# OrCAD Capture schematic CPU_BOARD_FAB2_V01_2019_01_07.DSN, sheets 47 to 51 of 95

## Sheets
47 024 BDX-DE LPC,SPI,GPIO,INT_1: size B
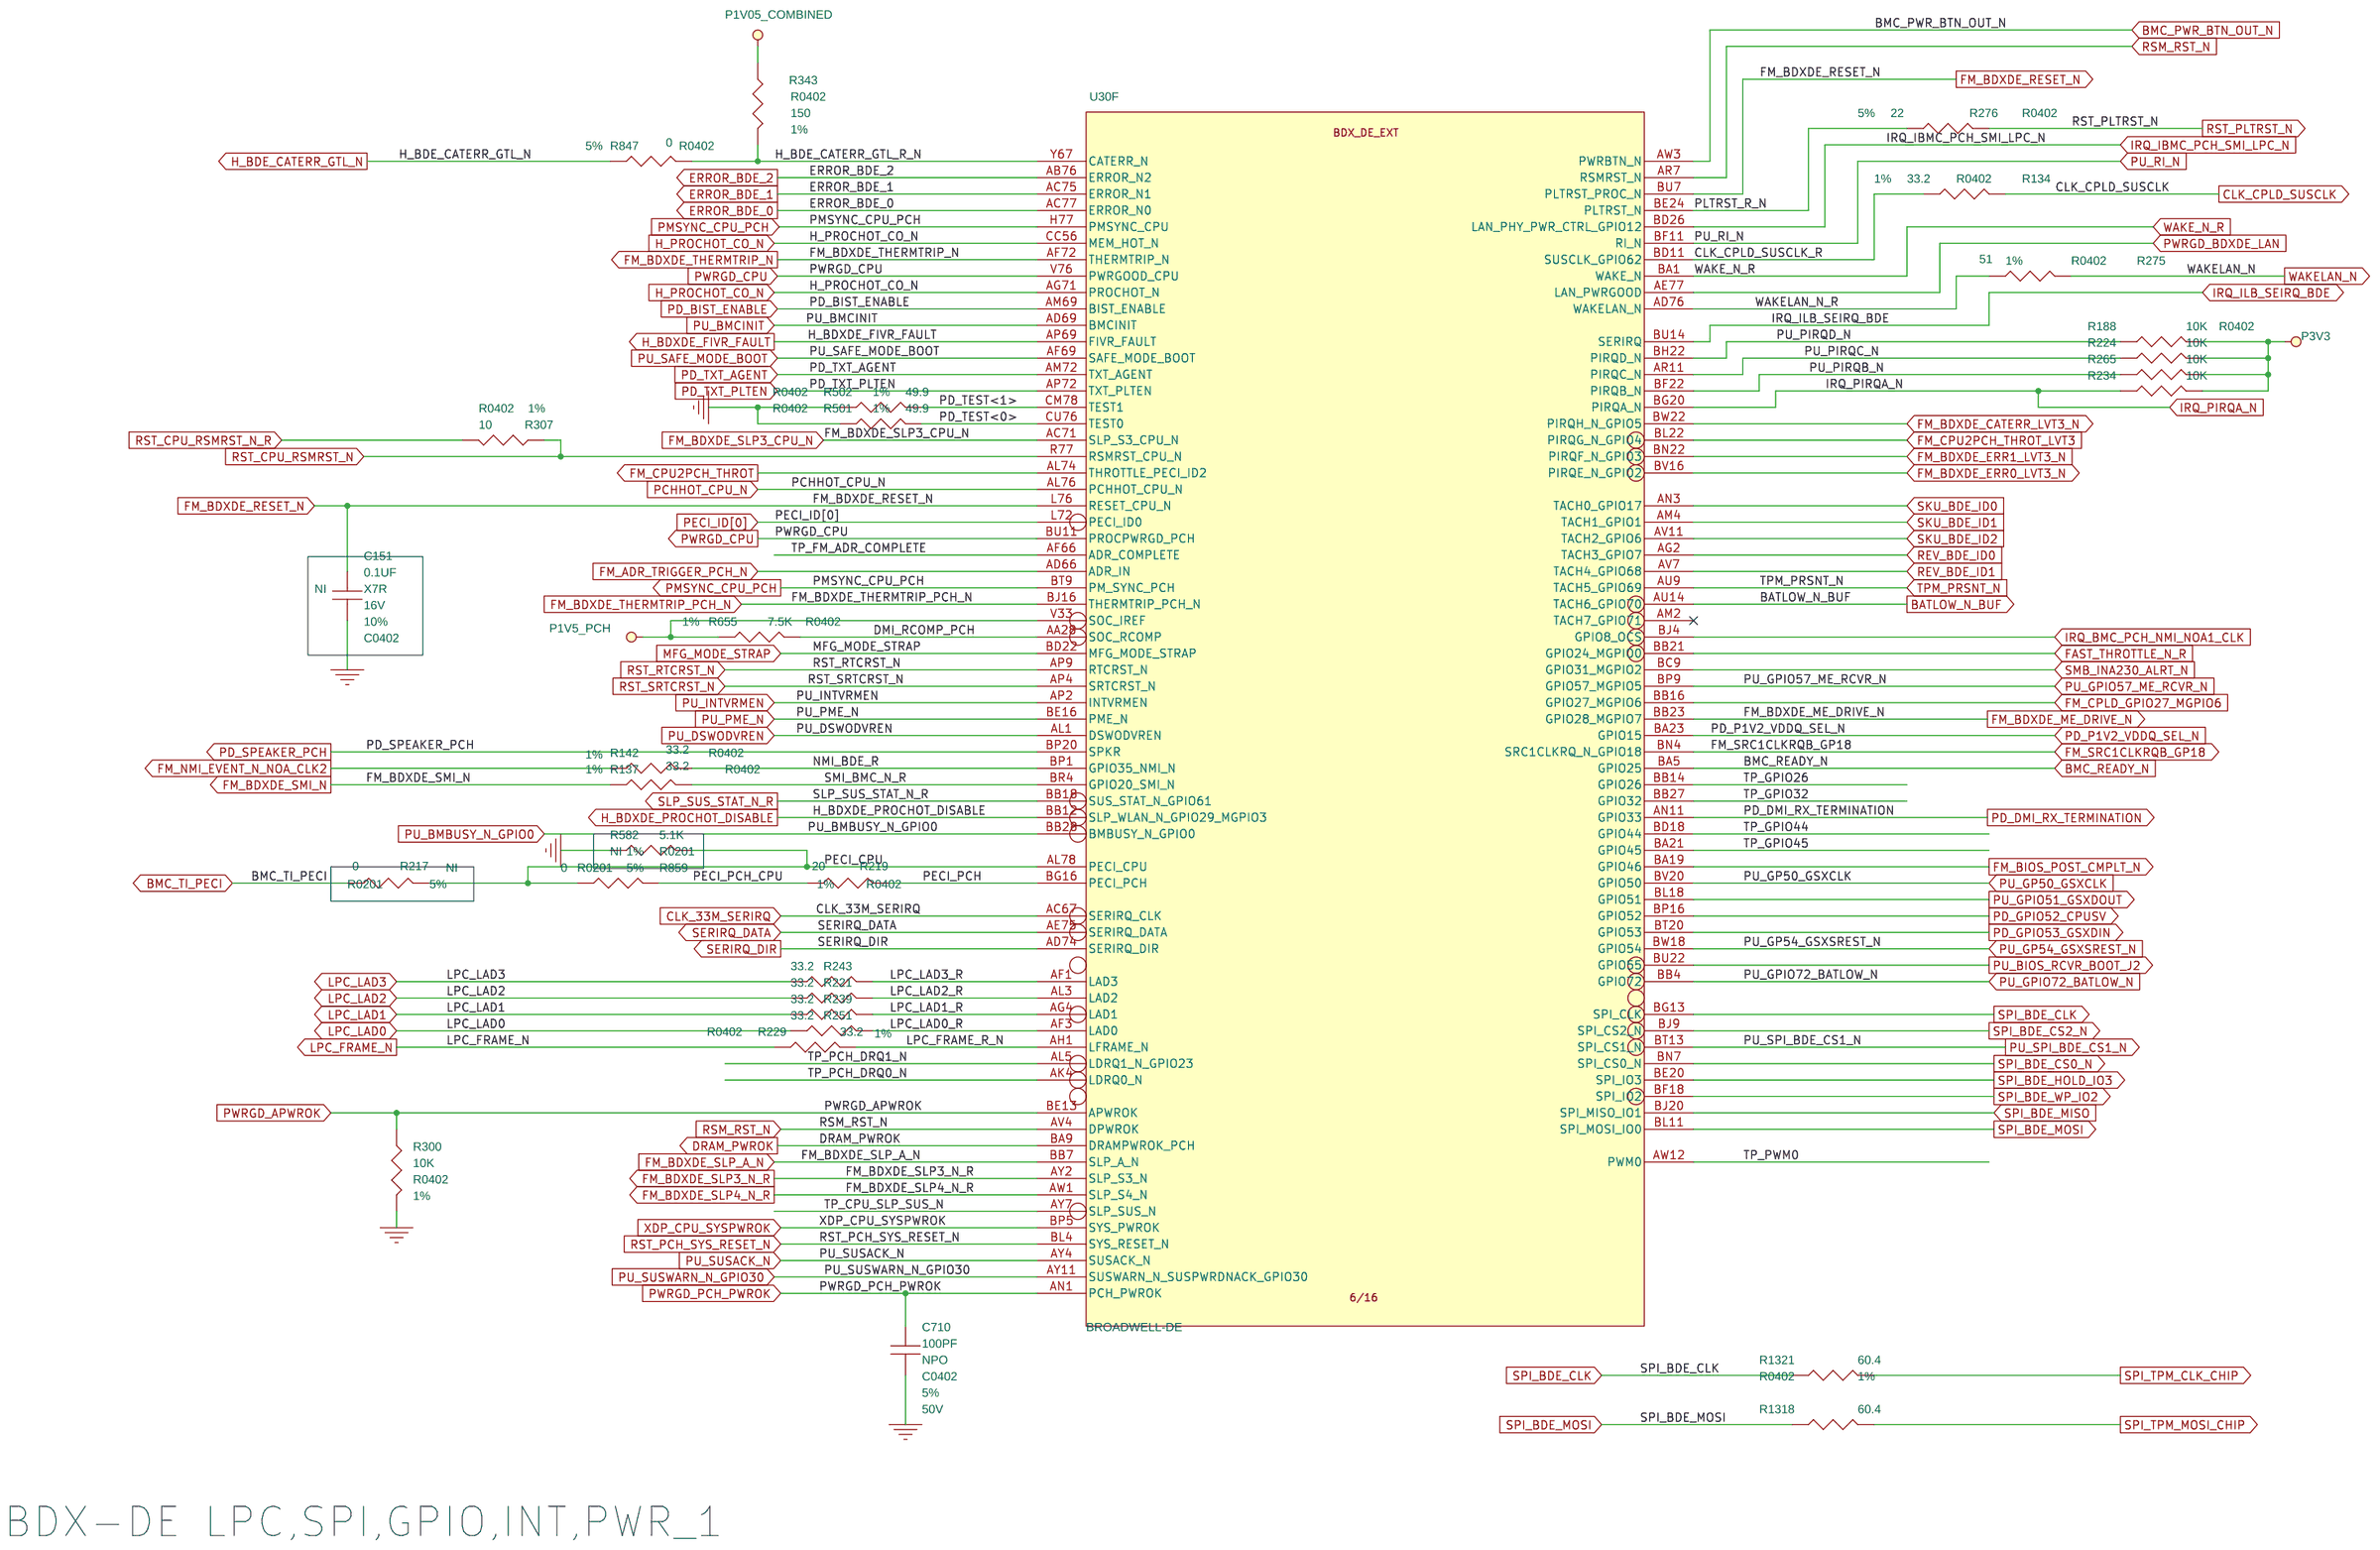
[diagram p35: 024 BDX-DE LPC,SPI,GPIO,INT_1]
48 026 BDX-DE UART,MGNT,INT,SVID_1: size B
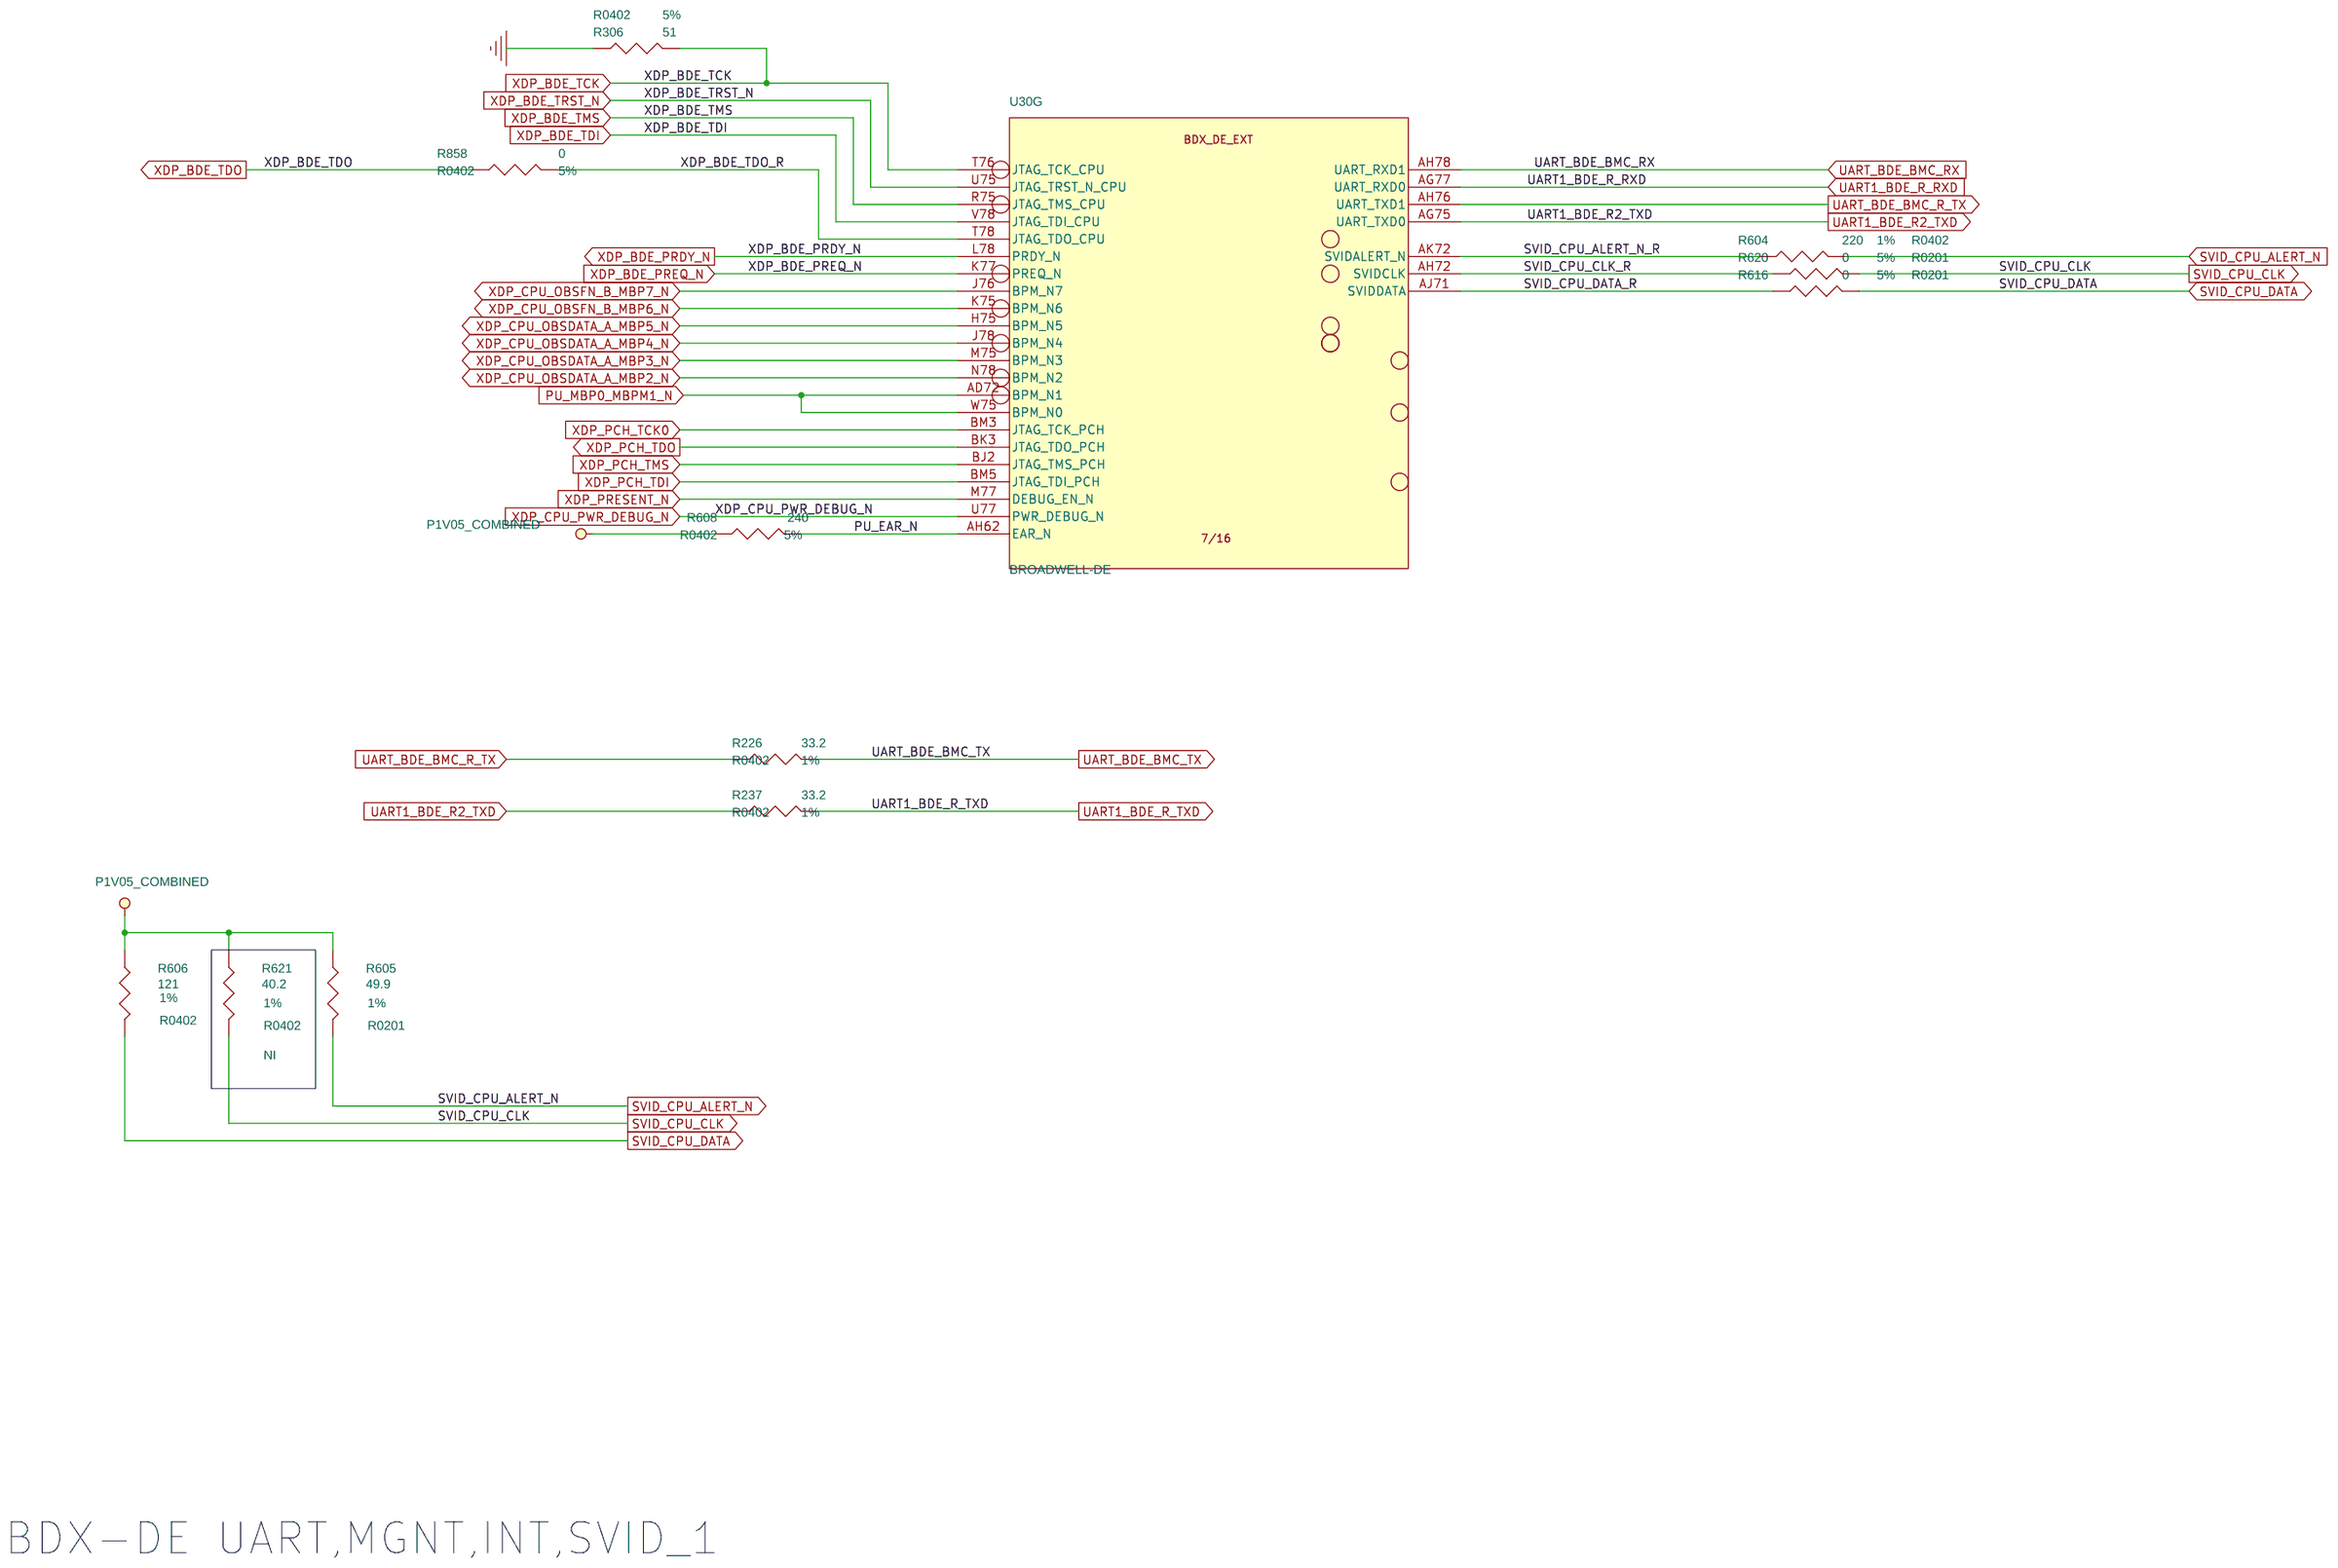
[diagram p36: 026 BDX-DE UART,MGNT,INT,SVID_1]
49 028 BDX-DE CLK: size B
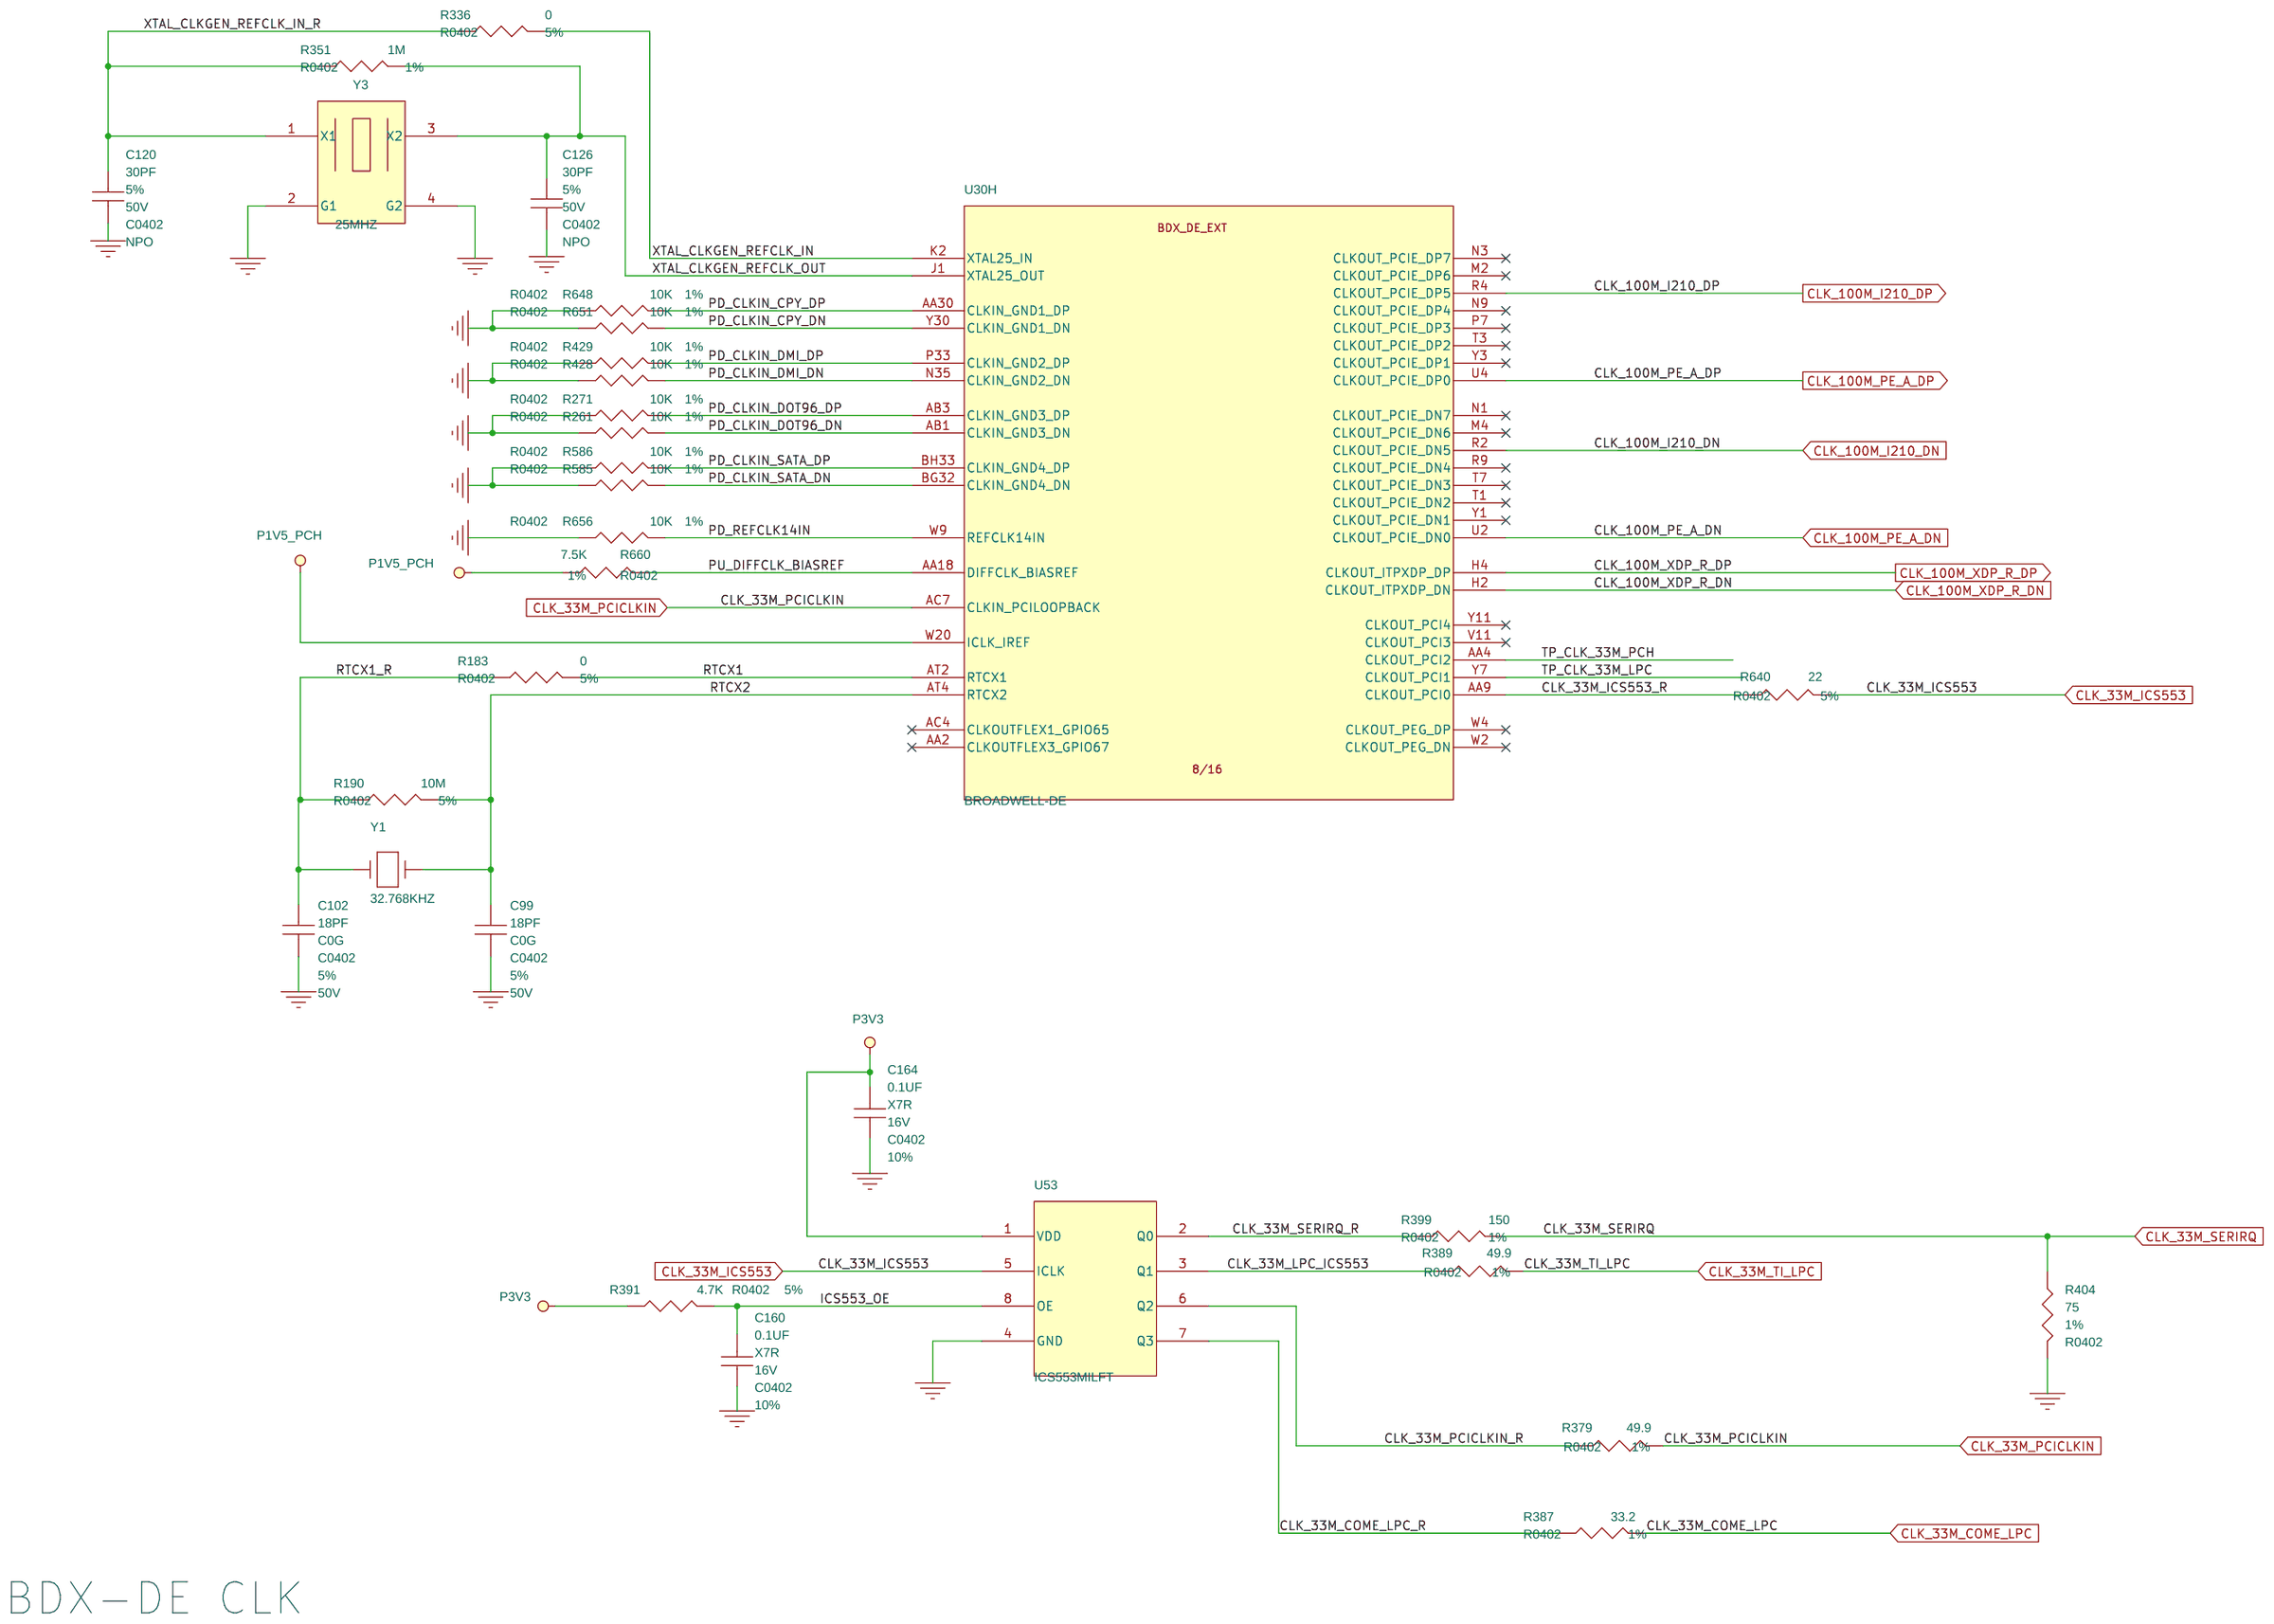
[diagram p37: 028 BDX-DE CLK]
50 029 BDX-DE TEST: size B
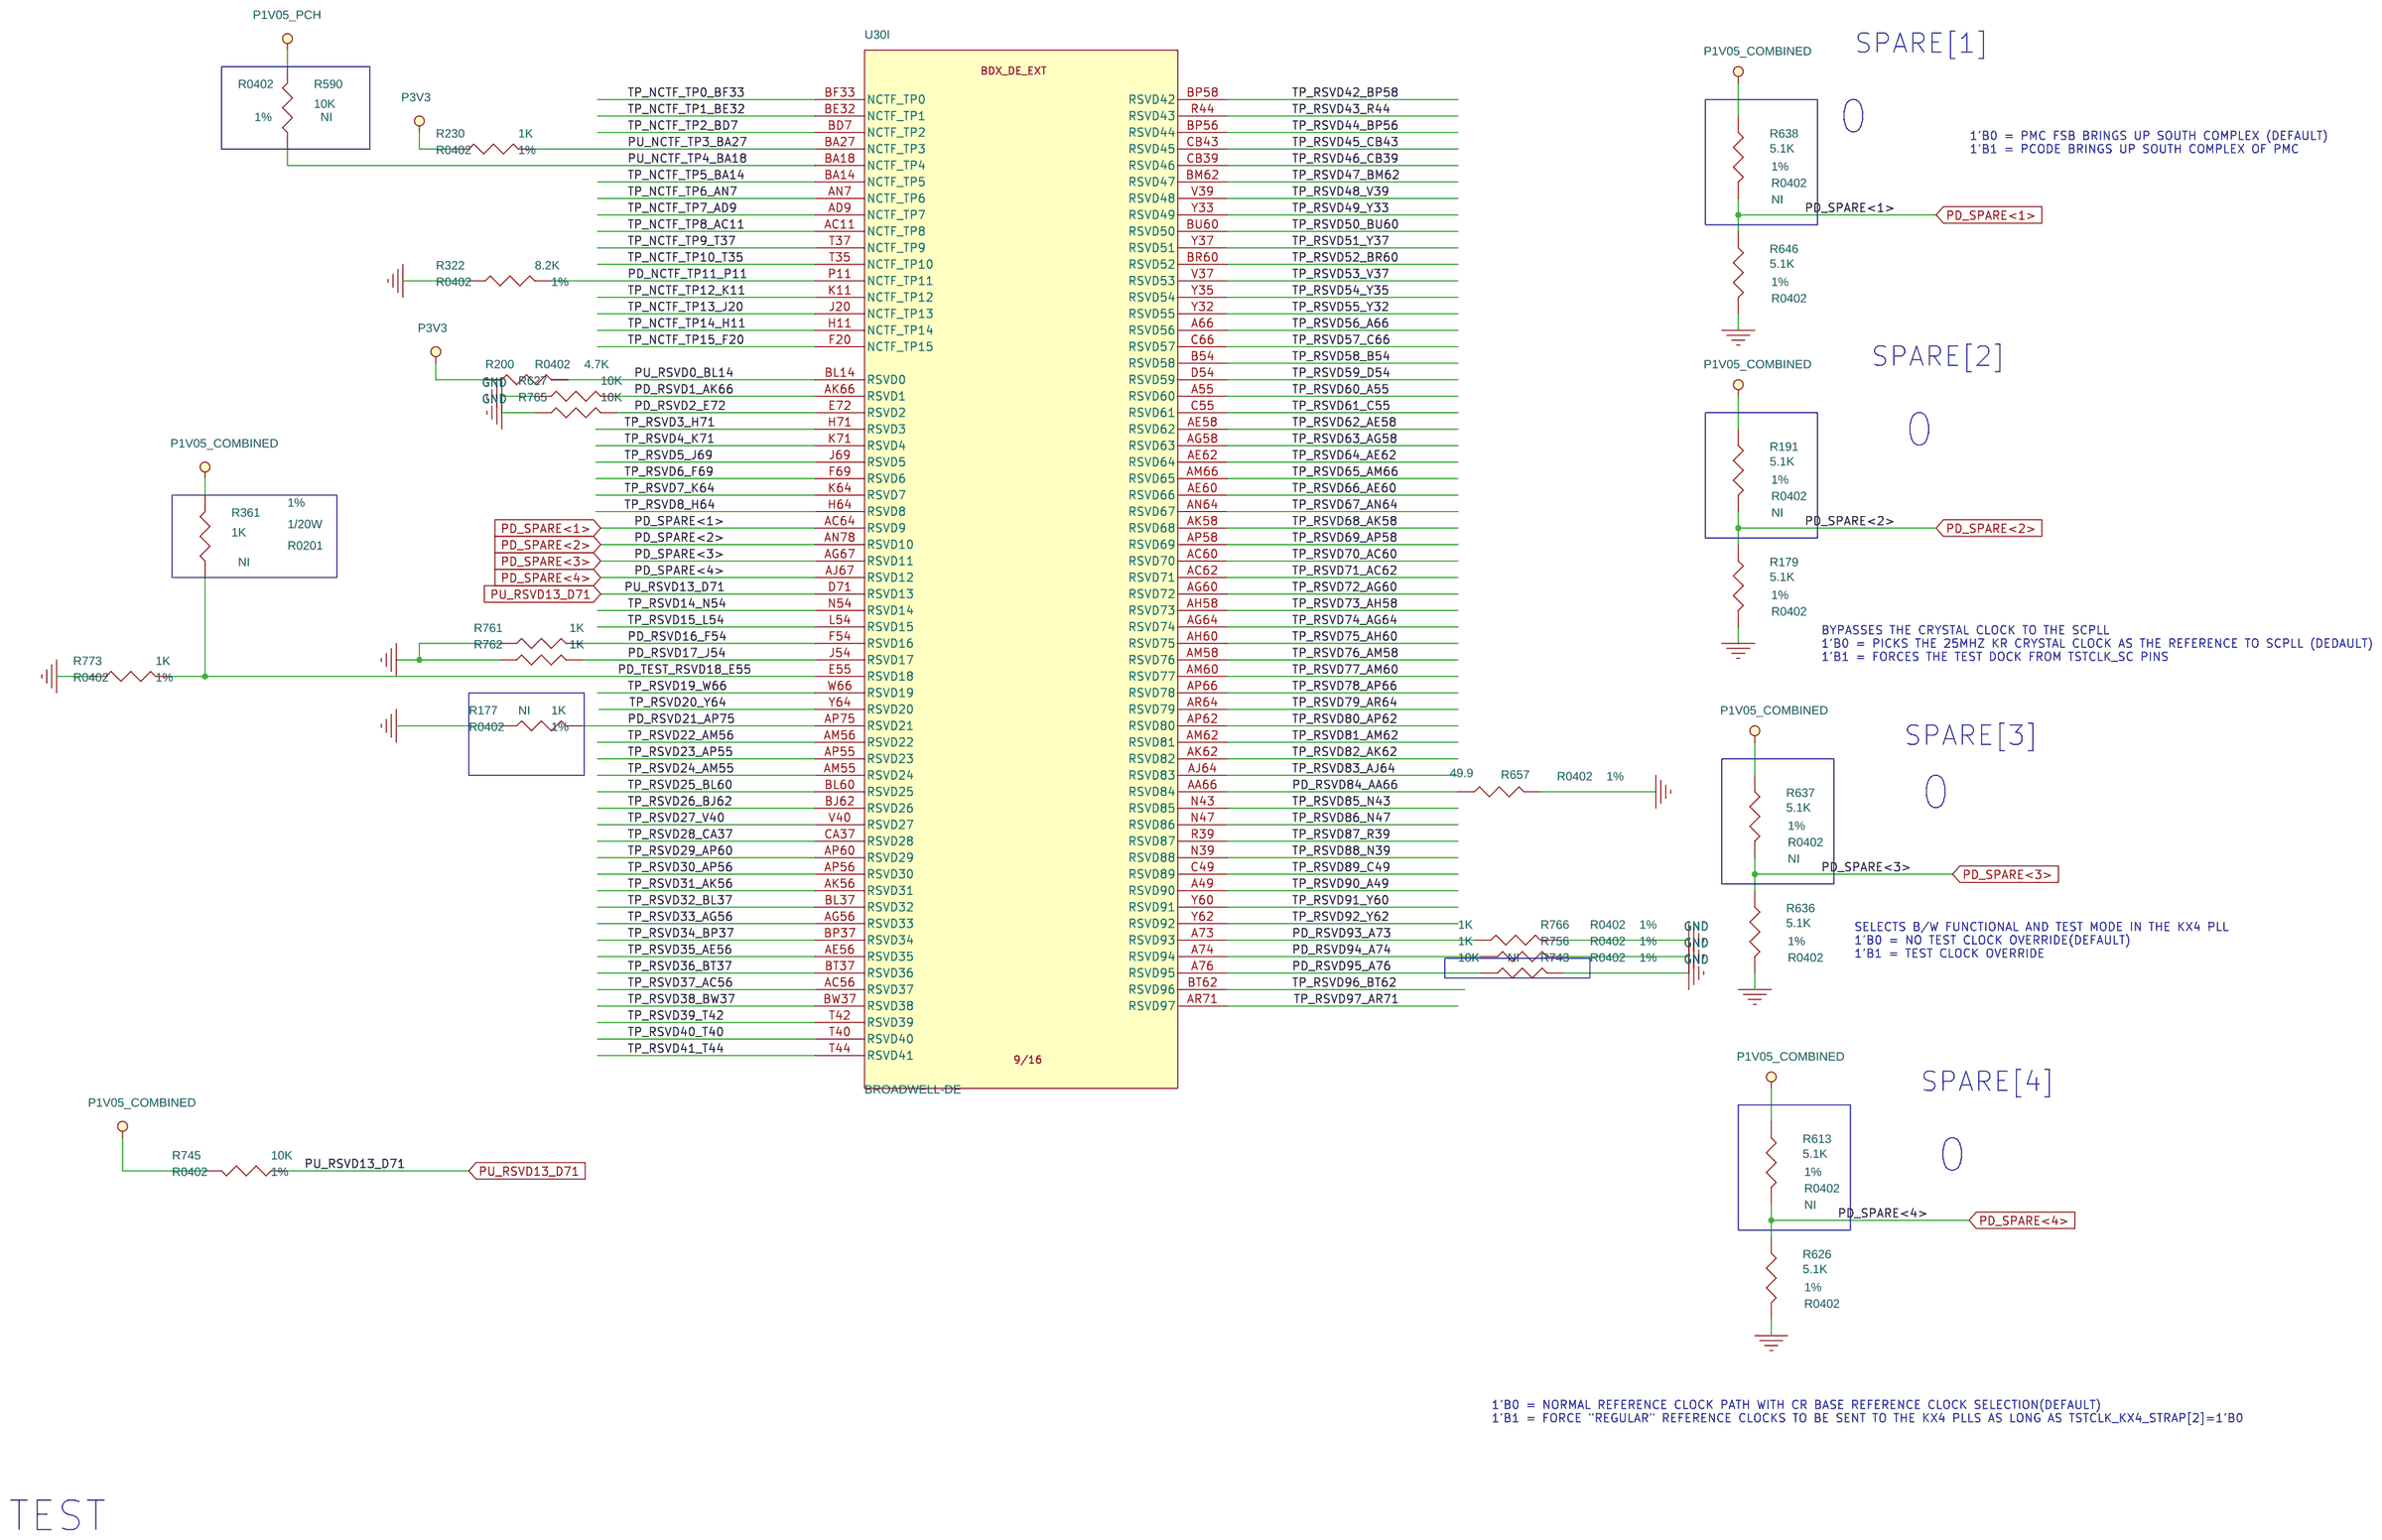
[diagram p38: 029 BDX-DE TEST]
51 031 BDX-DE POWER_1: size B
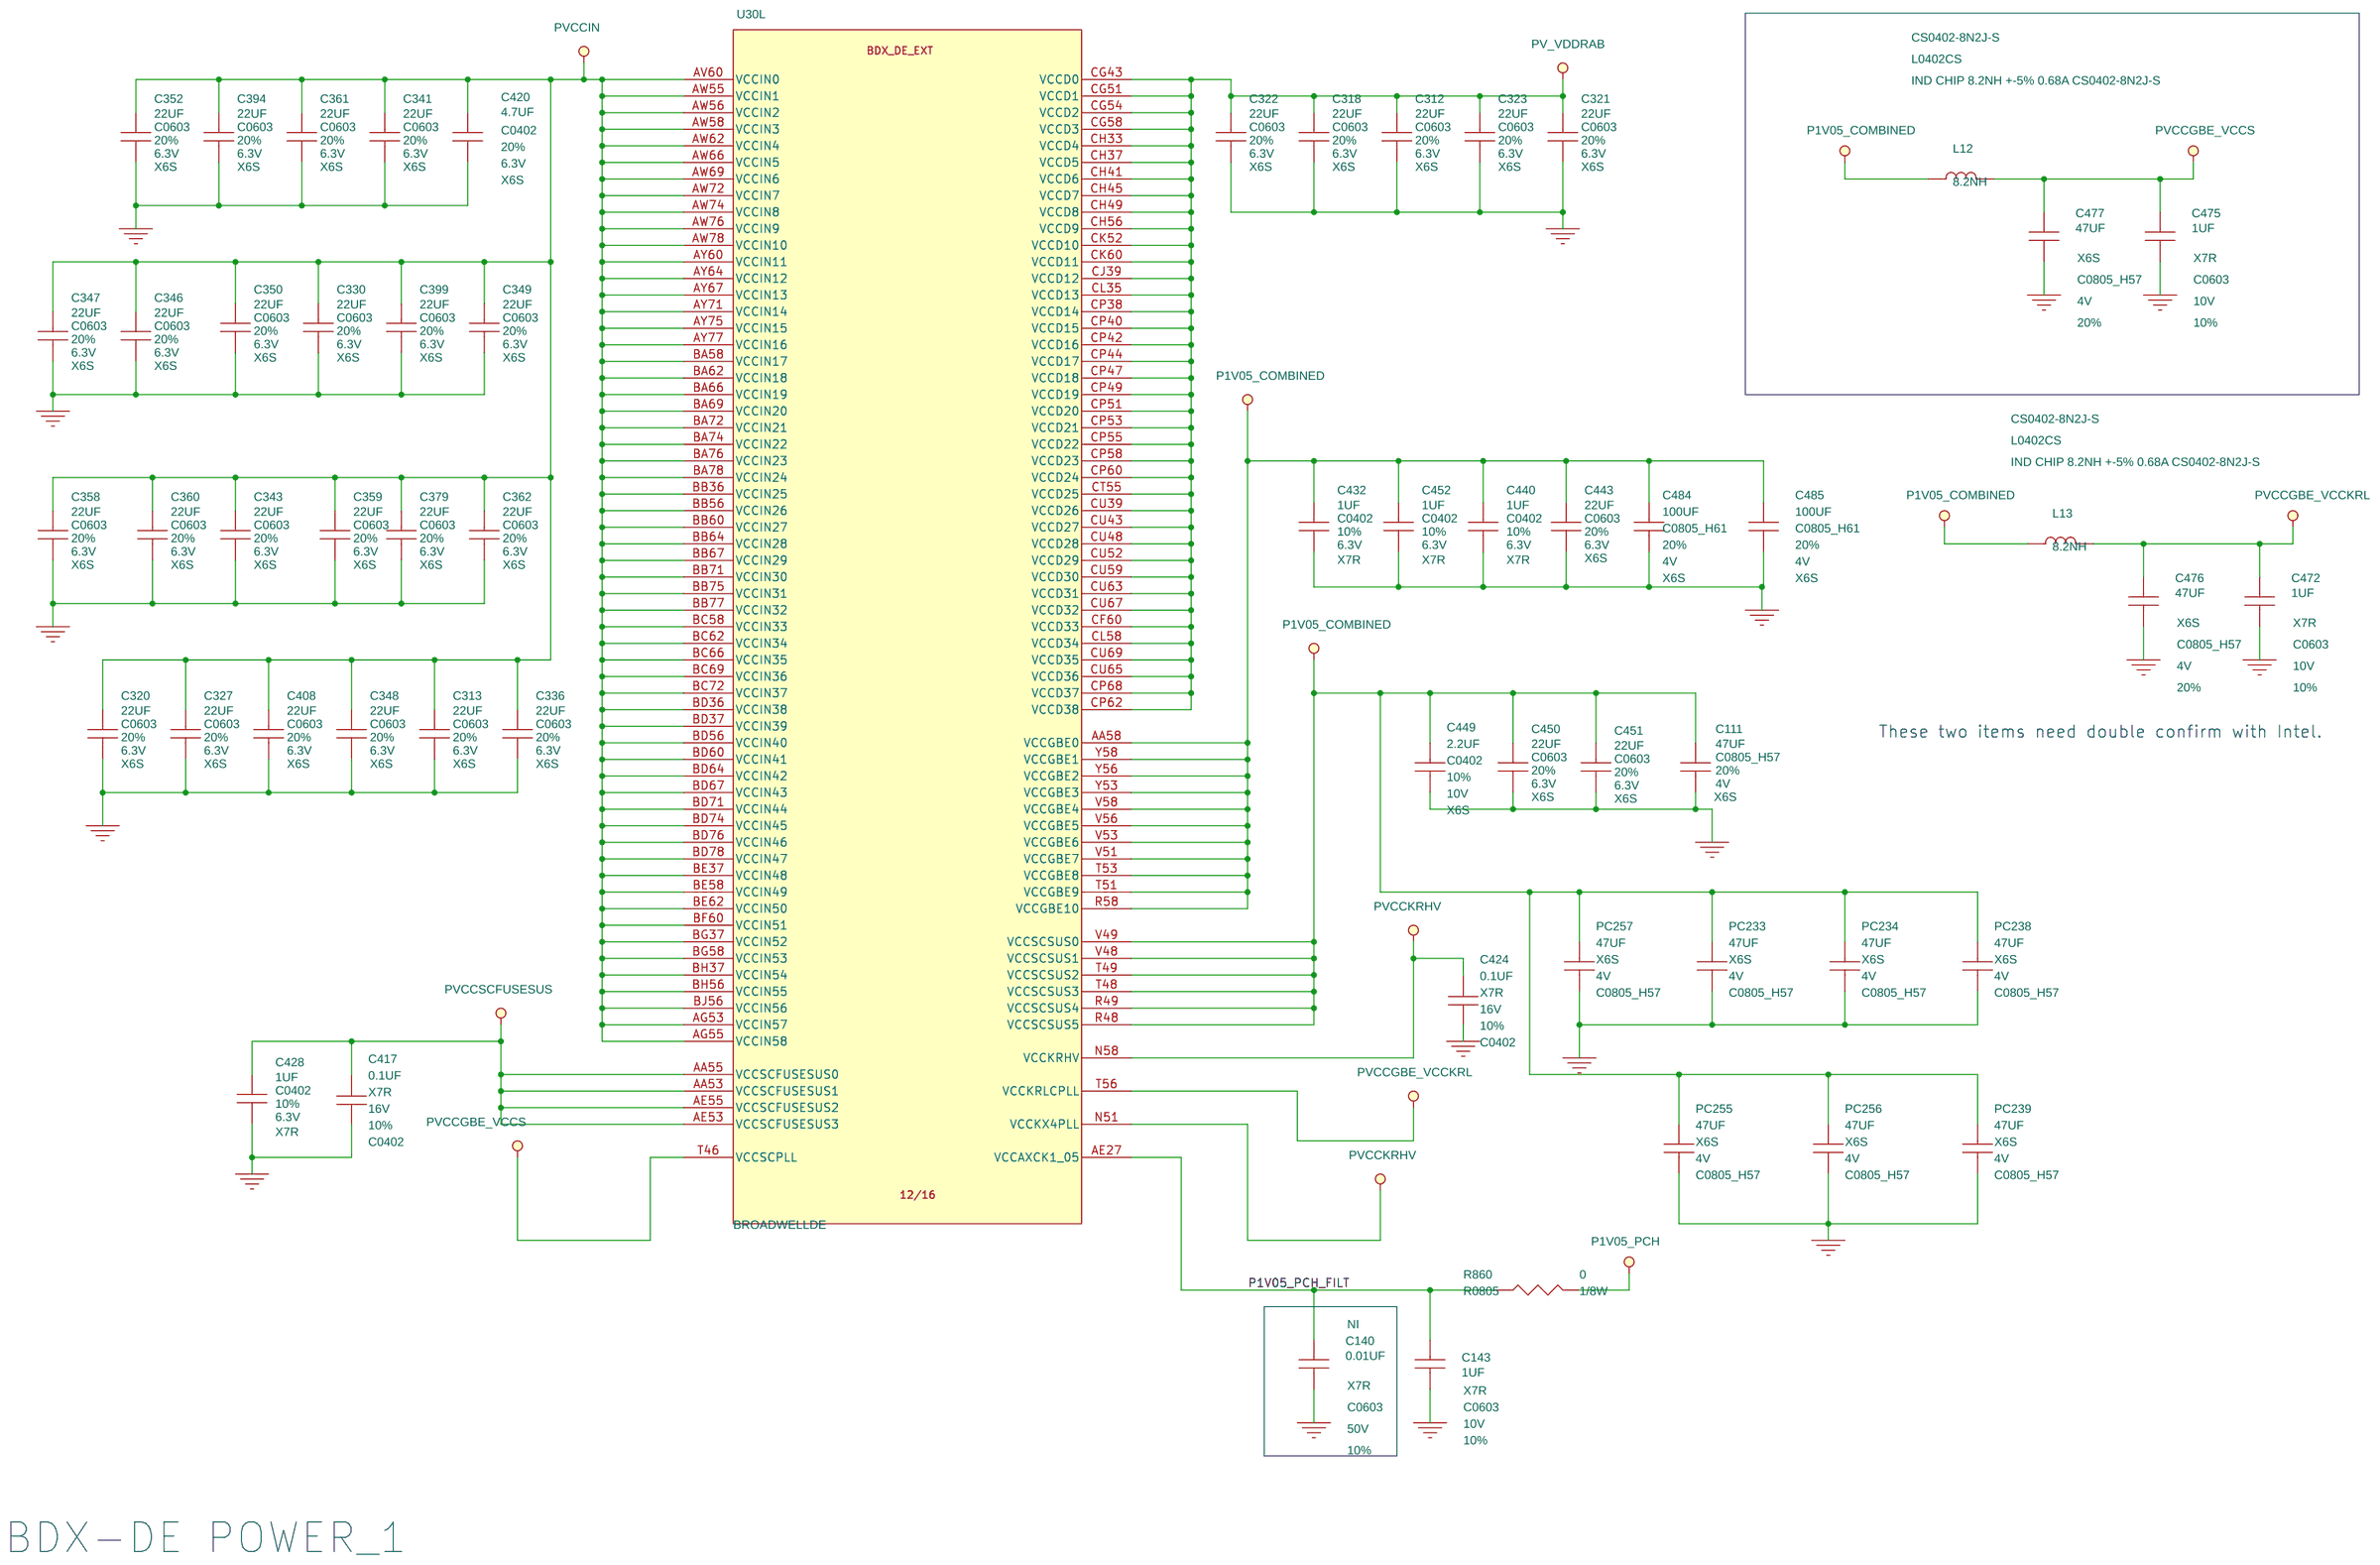
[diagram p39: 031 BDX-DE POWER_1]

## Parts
sheet 023 BDX-DE SATA, USB2, USB3
U30  BROADWELL-DE  [BGA1667]  (sections A,B,C,D,E,F,G,H,I,J,K,L,M,N,O,P)
sheet 024 BDX-DE LPC,SPI,GPIO,INT_1
C151  0.1UF  [C0402]
C710  100PF  [C0402]
R134  33.2  [R0402]
R137  33.2  [R0402]
R142  33.2  [R0402]
R188  10K  [R0402]
R217  0  [R0201]
R219  20  [R0402]
R221  33.2  [R0402]
R224  10K  [R0402]
R229  33.2  [R0402]
R234  10K  [R0402]
R239  33.2  [R0402]
R243  33.2  [R0402]
R251  33.2  [R0402]
R265  10K  [R0402]
R275  51  [R0402]
R276  22  [R0402]
R300  10K  [R0402]
R307  10  [R0402]
R343  150  [R0402]
R501  49.9  [R0402]
R502  49.9  [R0402]
R582  5.1K  [R0201]
R655  7.5K  [R0402]
R847  0  [R0402]
R859  0  [R0201]
R1318  60.4  [R0402]
R1321  60.4  [R0402]
sheet 026 BDX-DE UART,MGNT,INT,SVID_1
R226  33.2  [R0402]
R237  33.2  [R0402]
R306  51  [R0402]
R604  220  [R0402]
R605  49.9  [R0201]
R606  121  [R0402]
R608  240  [R0402]
R616  0  [R0201]
R620  0  [R0201]
R621  40.2  [R0402]
R858  0  [R0402]
sheet 028 BDX-DE CLK
C99  18PF  [C0402]
C102  18PF  [C0402]
C120  30PF  [C0402]
C126  30PF  [C0402]
C160  0.1UF  [C0402]
C164  0.1UF  [C0402]
R183  0  [R0402]
R190  10M  [R0402]
R261  10K  [R0402]
R271  10K  [R0402]
R336  0  [R0402]
R351  1M  [R0402]
R379  49.9  [R0402]
R387  33.2  [R0402]
R389  49.9  [R0402]
R391  4.7K  [R0402]
R399  150  [R0402]
R404  75  [R0402]
R428  10K  [R0402]
R429  10K  [R0402]
R585  10K  [R0402]
R586  10K  [R0402]
R640  22  [R0402]
R648  10K  [R0402]
R651  10K  [R0402]
R656  10K  [R0402]
R660  7.5K  [R0402]
U53  ICS553MILFT  [SOIC8]
Y1  32.768KHZ  [X_2S_9H03200012_2X1-2]
Y3  25MHZ  [X_4S_8Z25000020_2-5X2]
sheet 029 BDX-DE TEST
R177  1K  [R0402]
R179  5.1K  [R0402]
R191  5.1K  [R0402]
R200  4.7K  [R0402]
R230  1K  [R0402]
R322  8.2K  [R0402]
R361  1K  [R0201]
R590  10K  [R0402]
R613  5.1K  [R0402]
R626  5.1K  [R0402]
R627  10K  [R0402]
R636  5.1K  [R0402]
R637  5.1K  [R0402]
R638  5.1K  [R0402]
R646  5.1K  [R0402]
R657  49.9  [R0402]
R743  10K  [R0402]
R745  10K  [R0402]
R756  1K  [R0402]
R761  1K  [R0402]
R762  1K  [R0402]
R765  10K  [R0402]
R766  1K  [R0402]
R773  1K  [R0402]
sheet 031 BDX-DE POWER_1
C111  47UF  [C0805_H57]
C140  0.01UF  [C0603]
C143  1UF  [C0603]
C312  22UF  [C0603]
C313  22UF  [C0603]
C318  22UF  [C0603]
C320  22UF  [C0603]
C321  22UF  [C0603]
C322  22UF  [C0603]
C323  22UF  [C0603]
C327  22UF  [C0603]
C330  22UF  [C0603]
C336  22UF  [C0603]
C341  22UF  [C0603]
C343  22UF  [C0603]
C346  22UF  [C0603]
C347  22UF  [C0603]
C348  22UF  [C0603]
C349  22UF  [C0603]
C350  22UF  [C0603]
C352  22UF  [C0603]
C358  22UF  [C0603]
C359  22UF  [C0603]
C360  22UF  [C0603]
C361  22UF  [C0603]
C362  22UF  [C0603]
C379  22UF  [C0603]
C394  22UF  [C0603]
C399  22UF  [C0603]
C408  22UF  [C0603]
C417  0.1UF  [C0402]
C420  4.7UF  [C0402]
C424  0.1UF  [C0402]
C428  1UF  [C0402]
C432  1UF  [C0402]
C440  1UF  [C0402]
C443  22UF  [C0603]
C449  2.2UF  [C0402]
C450  22UF  [C0603]
C451  22UF  [C0603]
C452  1UF  [C0402]
C472  1UF  [C0603]
C475  1UF  [C0603]
C476  47UF  [C0805_H57]
C477  47UF  [C0805_H57]
C484  100UF  [C0805_H61]
C485  100UF  [C0805_H61]
L12  8.2NH  [L0402CS]
L13  8.2NH  [L0402CS]
PC233  47UF  [C0805_H57]
PC234  47UF  [C0805_H57]
PC238  47UF  [C0805_H57]
PC239  47UF  [C0805_H57]
PC255  47UF  [C0805_H57]
PC256  47UF  [C0805_H57]
PC257  47UF  [C0805_H57]
R860  0  [R0805]

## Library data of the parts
U30 = BROADWELLDE: CPU(1667P)Broadwell-DE (FCBGA); CLASS: IC; Data: INT_Broadwell-DE_REV0_75.pdf; From_pj: S1M-MANSON; MATERIAL: IC; Manuf_name: INTEGRATED DEVICE TECHNOLOGY,INC.; Manuftr: INT; Part_Type: Tmp; Color: Default; Location X-Coordinate: 0; Location Y-Coordinate: 0; Power Pins Visible: False; Primitive: DEFAULT
C151 = CAP_NP: CAP CHIP 0.1U 16V(10%.X7R.0402); CLASS: DISCRETE; CMPLS_LVL: EP(V1); Data: MUR_LF_CAP SERIES_1.pdf; From_pj: S5A-TRAVIS; Lifecycle: Comp-Approve; MATERIAL: X7R; Manuf_PN: WBM155R71C104K; Manuf_name: MURATA ERIE N.A. INC TAIWAN BRANCH Okayama Murata Mfg.Co..Ltd. Wakura Murata Mfg; Manufacturer: MUR; Manuftr: MUR; Not_insert: NI; Part_Type: *LF_C0402; RD_CMPLS_LVL: EP(V1); ROOM: VR_P1V05_PCH; TOLERANCE: 10%; Top_bot: TOP; VOLTAGE: 16V; fp_ECN: 0402 SERIES_LL34.xls
C710 = CAP_NP: CAP CHIP 100P 50V(+-5%.NPO.0402); CLASS: DISCRETE; CMPLS_LVL: EP; Data: RHT_LF_CAP SERIES-4.pdf; From_pj: RS2-EASON; Lifecycle: Comp-Approve; MATERIAL: NPO; Manuf_PN: CC0402N101J3SST-S; Manuf_name: "RTECH TECHNOLOGY CO..LTD.(Compostar)"; Manuftr: RHT; Part_Type: *LF_C0402; TOLERANCE: 5%; VOLTAGE: 50V; fp_ECN: 0402 SERIES_LL34.xls
R134 R137 R142 R221 R226 R229 R237 R239 R243 R251 R387 = R: RES CHIP 33.2 1/16W +-1%(0402); CLASS: DISCRETE; CMPLS_LVL: EP; Data: CYN_LF_RL SERIES.pdf; From_pj: A06-EDISON; Lifecycle: Comp-Approve; MATERIAL: CHIP; Manuf_PN: RR0510S-33R2-FN; Manuf_name: CYNTEC CO.. LTD.; Manuftr: CYN; Part_Type: *LF_Resistor; TOLERANCE: 1%; WATTAGE: 1/16W; fp_ECN: 0402 SERIES_LL34.xls
R188 R224 R234 R261 R265 R271 R300 R428 R429 R585 R586 R627 R648 R651 R656 R745 R765 = R: RES CHIP 10K 1/16W +-1% (0402); CLASS: DISCRETE; CMPLS_LVL: EP; Data: WTC_LF_WR SERIES.pdf; From_pj: S82; Lifecycle: Comp-Approve; MATERIAL: CHIP; Manuf_PN: RR0510S-103-FN; Manuf_name: CYNTEC CO.. LTD.; Manuftr: CYN; Part_Type: *LF_Resistor; Status: Preferred; TOLERANCE: 1%; WATTAGE: 1/16W; fp_ECN: 0402 SERIES_LL34.xls
R217 = R: RES CHIP 0(1/20W,+-5%,0201); CLASS: DISCRETE; CMPLS_LVL: EP(V1); Data: YGO_RC0201JR-070RL.pdf; From_pj: F07-HENRY; Lifecycle: Comp-Approve; MATERIAL: CHIP; Manuf_PN: RC0201JR-130RL; Manuf_name: YAGEO CORPORATION; Manuftr: YGO; Not_insert: NI; Part_Type: *LF_Resistor; RD_CMPLS_LVL: EP(V1); TOLERANCE: 5%; WATTAGE: 1/20W; fp_ECN: DCN-ALL 0201 RCL PART.doc
R219 = R: RES CHIP 20 1/16W +-1% (0402); CLASS: DISCRETE; CMPLS_LVL: EP; Data: RHT_LF_RES SERIES.pdf; Lifecycle: Comp-Approve; MATERIAL: CHIP; Manuf_PN: RR0510S-20R0-FN; Manuf_name: CYNTEC CO.. LTD.; Manuftr: CYN; Part_Type: *LF_Resistor; Standard: ##; Status: Preferred; TOLERANCE: 1%; WATTAGE: 1/16W; fp_ECN: 0402 SERIES_LL34.xls
R275 = R: RES CHIP 51 1/16W +-1% (0402); CLASS: DISCRETE; CMPLS_LVL: EP; Data: RHT_LF_RES SERIES-2.pdf; From_pj: JN1-LUNG; MATERIAL: CHIP; Manuf_PN: CR0251R0F002S; Manuf_name: RTECH TECHNOLOGY CO..LTD. (Compostar); Manuftr: RHT; Part_Type: *LF_Resistor; TOLERANCE: 1%; WATTAGE: 1/16W; fp_ECN: 0402 SERIES_LL34.xls
R276 R640 = R: RES CHIP 22 1/16W 5%(0402); CLASS: DISCRETE; CMPLS_LVL: EP; Data: CYN_LF_RL SERIES.pdf; From_pj: S57-HOWER; Lifecycle: Comp-Approve; MATERIAL: CHIP; Manuf_PN: RR0510S-220-JN; Manuf_name: CYNTEC CO.. LTD.; Manuftr: CYN; Part_Type: *LF_Resistor; Status: Preferred; TOLERANCE: 5%; WATTAGE: 1/16W; fp_ECN: 0402 SERIES_LL34.xls
R307 = R: RES CHIP 10 1/16W +-1%(0402); CLASS: DISCRETE; CMPLS_LVL: EP; Data: TAI_LF_RM SERIES-3.pdf; From_pj: RS2-MATT; MATERIAL: CHIP; Manuf_PN: RM04FTN10R0; Manuf_name: TA-I TECHNOLOGY CO..LTD.; Manuftr: TAI; Part_Type: *LF_Resistor; TOLERANCE: 1%; WATTAGE: 1/16W; fp_ECN: 0402 SERIES_LL34.xls
R343 R399 = R: RES CHIP 150 1/16W +-1%(0402); CLASS: DISCRETE; CMPLS_LVL: EP; Data: WTC_LF_WR SERIES.pdf; From_pj: S07-CT; Lifecycle: Comp-Approve; MATERIAL: CHIP; Manuf_PN: RR0510S-151-FN; Manuf_name: CYNTEC CO.. LTD.; Manuftr: CYN; Part_Type: *LF_Resistor; Status: Preferred; TOLERANCE: 1%; WATTAGE: 1/16W; fp_ECN: 0402 SERIES_LL34.xls
R379 R389 R501 R502 R657 = R: RES CHIP 49.9 1/16W +-1% (0402); CLASS: DISCRETE; CMPLS_LVL: EP; Data: WTC_LF_WR SERIES.pdf; Lifecycle: Comp-Approve; MATERIAL: CHIP; Manuf_PN: RR0510S-49R9-FN; Manuf_name: CYNTEC CO.. LTD.; Manuftr: CYN; Part_Type: *LF_Resistor; Status: Preferred; TOLERANCE: 1%; WATTAGE: 1/16W; fp_ECN: 0402 SERIES_LL34.xls
R582 = R: RES CHIP 5.1K 1/20W +-1%(0201); CLASS: DISCRETE; CMPLS_LVL: EP(V1); Data: YGO_LF_RES SERIES.pdf; From_pj: GD1-JACK; Lifecycle: Comp-Approve; MATERIAL: CHIP; Manuf_PN: RC0201FR-075K1L; Manuf_name: YAGEO CORPORATION; Manuftr: YGO; Not_insert: NI; Part_Type: *LF_Resistor; RD_CMPLS_LVL: EP(V1); Standard: End of Design; TOLERANCE: 1%; WATTAGE: 1/20W; fp_ECN: DCN-all 0201 RCL part.doc
R655 R660 = R: RES CHIP 7.5K 1/16W +-1% (0402); CLASS: DISCRETE; CMPLS_LVL: EP; Data: WTC_LF_WR SERIES-4.pdf; From_pj: S93-MARTIN; MATERIAL: CHIP; Manuf_PN: WR04X7501FTL; Manuf_name: WALSIN TECHNOLOGY CORPORATION; Manuftr: WTC; Part_Type: *LF_Resistor; TOLERANCE: 1%; WATTAGE: 1/16W; fp_ECN: 0402 SERIES_LL34.xls
R183 R336 R847 R858 = R: RESISTOR CHIP 0 1/16W +-5%(0402); CLASS: DISCRETE; CMPLS_LVL: EP; Data: WTC_LF_WR SERIES.pdf; Lifecycle: Comp-Approve; MATERIAL: CHIP; Manuf_PN: RR0510X-000-XN; Manuf_name: CYNTEC CO.. LTD.; Manuftr: CYN; Part_Type: *LF_Resistor; Status: Preferred; TOLERANCE: 5%; WATTAGE: 1/16W; fp_ECN: 0402 SERIES_LL34.xls
R616 R620 R859 = R: RES CHIP 0(1/20W,+-5%,0201); CLASS: DISCRETE; CMPLS_LVL: EP(V1); Data: YGO_RC0201JR-070RL.pdf; From_pj: F07-HENRY; Lifecycle: Comp-Approve; MATERIAL: CHIP; Manuf_PN: RC0201JR-130RL; Manuf_name: YAGEO CORPORATION; Manuftr: YGO; Part_Type: *LF_Resistor; RD_CMPLS_LVL: EP(V1); TOLERANCE: 5%; WATTAGE: 1/20W; fp_ECN: DCN-ALL 0201 RCL PART.doc
R1318 R1321 = R: RES CHIP 60.4 1/16W +-1%(0402); CLASS: DISCRETE; CMPLS_LVL: EP; Data: RHT_LF_RES SERIES.pdf; Lifecycle: Comp-Approve; MATERIAL: CHIP; Manuf_PN: RR0510S-60R4-FN; Manuf_name: CYNTEC CO.. LTD.; Manuftr: CYN; Part_Type: *LF_Resistor; Status: Preferred; TOLERANCE: 1%; TOP_BOT: TOP; WATTAGE: 1/16W; fp_ECN: 0402 SERIES_LL34.xls
R306 = R: RES CHIP 51 1/16W +-5%(0402); CLASS: DISCRETE; CMPLS_LVL: EP; Data: TAI_LF_RM SERIES.pdf; Lifecycle: Comp-Approve; MATERIAL: CHIP; Manuf_PN: RR0510S-510-JN; Manuf_name: CYNTEC CO.. LTD.; Manuftr: CYN; Part_Type: *LF_Resistor; Status: Preferred; TOLERANCE: 5%; WATTAGE: 1/16W; fp_ECN: 0402 SERIES_LL34.xls
R604 = R: RES CHIP 220 1/16W +-1%(0402); CLASS: DISCRETE; CMPLS_LVL: EP; Data: TAI_LF_RM SERIES-2.pdf; From_pj: S2F-JOSEPH; Lifecycle: Comp-Approve; MATERIAL: CHIP; Manuf_PN: RM04FTN2200; Manuf_name: TA-I TECHNOLOGY CO..LTD.; Manuftr: TAI; Part_Type: *LF_Resistor; TOLERANCE: 1%; WATTAGE: 1/16W; fp_ECN: 0402 SERIES_LL34.xls
R605 = R: RES CHIP 49.9 1/20W +-1%(0201); CLASS: DISCRETE; CMPLS_LVL: EP(V1); Data: CYN_RL SERIES_revB0.pdf; From_pj: GD1-JACK; Lifecycle: Comp-Approve; MATERIAL: CHIP; Manuf_PN: RR0306S-49R9-FN; Manuf_name: CYNTEC CO., LTD.; Manuftr: CYN; Part_Type: *LF_Resistor; RD_CMPLS_LVL: EP(V1); TOLERANCE: 1%; WATTAGE: 1/20W; fp_ECN: DCN-all 0201 RCL part.doc
R606 = R: RES CHIP 121 1/16W +-1%(0402); CLASS: DISCRETE; CMPLS_LVL: EP; Data: RHT_LF_RES SERIES.pdf; From_pj: S07-CT; Lifecycle: Comp-Approve; MATERIAL: CHIP; Manuf_PN: RR0510S-1210-FN; Manuf_name: CYNTEC CO.. LTD.; Manuftr: CYN; Part_Type: *LF_Resistor; Status: Preferred; TOLERANCE: 1%; WATTAGE: 1/16W; fp_ECN: 0402 SERIES_LL34.xls
R608 = R: RES CHIP 240 1/16W +-5%(0402); CLASS: DISCRETE; CMPLS_LVL: EP; Data: YGO_RC0402 SERIES.pdf; From_pj: TU1B-MARTIN; Lifecycle: Comp-Approve; MATERIAL: CHIP; Manuf_PN: RC0402JR-07240RL; Manuf_name: YAGEO CORPORATION; Manuftr: YGO; Part_Type: *LF_Resistor; RD_CMPLS_LVL: EP; TOLERANCE: 5%; WATTAGE: 1/16W; fp_ECN: 0402 SERIES_LL34.xls
R621 = R: RES CHIP 40.2 1/16W +-1%(0402); CLASS: DISCRETE; CMPLS_LVL: EP(V1); Data: WTC_LF_WR SERIES.pdf; Lifecycle: Comp-Approve; MATERIAL: CHIP; Manuf_PN: RR0510S-40R2-FN; Manuf_name: CYNTEC CO.. LTD.; Manuftr: CYN; Not_insert: NI; Part_Type: *LF_Resistor; RD_CMPLS_LVL: EP(V1); TOLERANCE: 1%; WATTAGE: 1/16W; fp_ECN: 0402 SERIES_LL34.xls
C99 C102 = CAP_NP: CAP CHIP 18P 50V(+-5% C0G 0402); CLASS: DISCRETE; CMPLS_LVL: EP; Data: MUR_LF_CAP SERIES_1.pdf; From_pj: LB6-JAMES; Lifecycle: Comp-Release Qty; MATERIAL: C0G; Manuf_PN: GRM1555C1H180J; Manuf_name: MURATA ERIE N.A. INC TAIWAN BRANCH Okayama Murata Mfg.Co..Ltd. Wakura Murata Mfg; Manuftr: MUR; Part_Type: *LF_C0402; TOLERANCE: 5%; VOLTAGE: 50V; fp_ECN: 0402 SERIES_LL34.xls
C120 C126 = CAP_NP: CAP CHIP 30P 50V(+-5% NPO 0402); CLASS: DISCRETE; CMPLS_LVL: EP; Data: TDK_C Series_1.pdf; From_pj: S65-JOSEPH; Lifecycle: Comp-Approve; MATERIAL: NPO; Manuf_PN: C1005C0G1H300J-B; Manuf_name: TDK TAIWAN CORP.TDK XIAMEN CO..LTD; Manuftr: TDK; Part_Type: *LF_C0402; TOLERANCE: 5%; VOLTAGE: 50V; fp_ECN: 0402 SERIES_LL34.xls
C160 C164 = CAP_NP: CAP CHIP 0.1U 16V(10%.X7R.0402); CLASS: DISCRETE; CMPLS_LVL: EP(V1); Data: MUR_LF_CAP SERIES_1.pdf; From_pj: S5A-TRAVIS; Lifecycle: Comp-Approve; MATERIAL: X7R; Manuf_PN: WBM155R71C104K; Manuf_name: MURATA ERIE N.A. INC TAIWAN BRANCH Okayama Murata Mfg.Co..Ltd. Wakura Murata Mfg; Manufacturer: MUR; Manuftr: MUR; Part_Type: *LF_C0402; RD_CMPLS_LVL: EP(V1); ROOM: VR_P1V05_PCH; TOLERANCE: 10%; Top_bot: TOP; VOLTAGE: 16V; fp_ECN: 0402 SERIES_LL34.xls
R190 = R: RES CHIP 10M 1/16W +-5% (0402); CLASS: DISCRETE; CMPLS_LVL: EP; Data: WTC_LF_WR SERIES.pdf; MATERIAL: CHIP; Manuf_PN: RR0510S-106-JN; Manuf_name: CYNTEC CO.. LTD.; Manuftr: CYN; Part_Type: *LF_Resistor; Status: Preferred; TOLERANCE: 5%; WATTAGE: 1/16W; fp_ECN: 0402 SERIES_LL34.xls
R351 = R: RES CHIP 1M 1/16W +-1% (0402); CLASS: DISCRETE; CMPLS_LVL: EP; Data: TAI_LF_RM SERIES-3.pdf; From_pj: LU1-EASON; Lifecycle: Comp-Approve; MATERIAL: CHIP; Manuf_PN: RM04FTN1004; Manuf_name: TA-I TECHNOLOGY CO..LTD.; Manuftr: TAI; Part_Type: *LF_Resistor; TOLERANCE: 1%; WATTAGE: 1/16W; fp_ECN: 0402 SERIES_LL34.xls
R391 = R: RES CHIP 4.7K 1/16W +-5% (0402); CLASS: DISCRETE; CMPLS_LVL: EP; Data: WTC_LF_WR SERIES.pdf; Lifecycle: Comp-Approve; MATERIAL: CHIP; Manuf_PN: RR0510S-472-JN; Manuf_name: CYNTEC CO.. LTD.; Manufacturer: RLC; Manuftr: CYN; Part_Type: *LF_Resistor; Status: Preferred; TOLERANCE: 5%; WATTAGE: 1/16W; fp_ECN: 0402 SERIES_LL34.xls; top_bot: TOP
R404 = R: RES CHIP 75 1/16W +-1% (0402); CLASS: DISCRETE; CMPLS_LVL: EP; Data: WTC_LF_WR SERIES.pdf; From_pj: S07-CT; Lifecycle: Comp-Approve; MATERIAL: CHIP; Manuf_PN: RR0510S-750-FN; Manuf_name: CYNTEC CO.. LTD.; Manuftr: CYN; Part_Type: *LF_Resistor; Status: Normal; TOLERANCE: 1%; WATTAGE: 1/16W; fp_ECN: 0402 SERIES_LL34.xls
U53 = ICS553: IC (8P) ICS553MILFT(SOIC) L-F; CLASS: IC; CMPLS_LVL: EP; Data: ICS553_1.pdf; From_pj: LB6-JAMES; Lifecycle: Comp-Approve; MATERIAL: IC; Manuf_name: INTEGRATED CIRCUIT SYSTEM INC.; Manuftr: ICS; Part_Type: *LF_Chipset; RD_CMPLS_LVL: EP
Y1 = CRYSTAL: CRYSTAL SMD 32.768KHZ(+-20PPM,12.5PF); CLASS: IO; CMPLS_LVL: EP(V1); Data: TXC_9H03200012.pdf; From_pj: F09-TONY; Lifecycle: Comp-Approve; MATERIAL: MISC; Manuf_PN: 9H03200012; Manuf_name: TAIWAN X'TAL CORPATION; Manuftr: TXC; Part_Type: *LF_Misc; RD_CMPLS_LVL: EP(V1)
Y3 = X_4S_CX3225SB25000D0FPLCC: XTAL SMD 25MHZ(10PPM,18PF)8Z25000020; CLASS: IO; Data: TXC_8Z25000020.pdf; From_pj: F09-TONY; Lifecycle: P/N Release; MATERIAL: MISC; Manuf_PN: 8Z25000020; Manuf_name: TAIWAN X'TAL CORPATION (TXC Corporation); Manuftr: TXC; Part_Type: *LF_Misc; RD_CMPLS_LVL: EP(V1); Standard: Potential
R177 = R: RES CHIP 1K 1/16W +-1% (0402); CLASS: DISCRETE; CMPLS_LVL: EP; Data: WTC_LF_WR SERIES.pdf; Lifecycle: Comp-Approve; MATERIAL: CHIP; Manuf_PN: RR0510S-102-FN; Manuf_name: CYNTEC CO.. LTD.; Manuftr: CYN; Not_insert: NI; Part_Type: *LF_Resistor; Status: Preferred; TOLERANCE: 1%; WATTAGE: 1/16W; fp_ECN: 0402 SERIES_LL34.xls
R179 R626 R636 R646 = R: RES CHIP 5.1K 1/16W +-1%(0402); CLASS: DISCRETE; CMPLS_LVL: EP; Data: MAT_LF_RES SERIES.pdf; From_pj: S10-ANTONY; Lifecycle: Comp-Approve; MATERIAL: CHIP; Manuf_PN: RR0510S-512-FN; Manuf_name: CYNTEC CO.. LTD.; Manuftr: CYN; Part_Type: *LF_Resistor; Status: Normal; TOLERANCE: 1%; WATTAGE: 1/16W; fp_ECN: 0402 SERIES_LL34.xls
R191 R613 R637 R638 = R: RES CHIP 5.1K 1/16W +-1%(0402); CLASS: DISCRETE; CMPLS_LVL: EP; Data: MAT_LF_RES SERIES.pdf; From_pj: S10-ANTONY; Lifecycle: Comp-Approve; MATERIAL: CHIP; Manuf_PN: RR0510S-512-FN; Manuf_name: CYNTEC CO.. LTD.; Manuftr: CYN; Not_insert: NI; Part_Type: *LF_Resistor; Status: Normal; TOLERANCE: 1%; WATTAGE: 1/16W; fp_ECN: 0402 SERIES_LL34.xls
R200 = R: RES CHIP 4.7K 1/16W +-5% (0402); CLASS: DISCRETE; CMPLS_LVL: EP; Data: WTC_LF_WR SERIES.pdf; Lifecycle: Comp-Approve; MATERIAL: CHIP; Manuf_PN: RR0510S-472-JN; Manuf_name: CYNTEC CO.. LTD.; Manuftr: CYN; Part_Type: *LF_Resistor; Status: Preferred; TOLERANCE: 5%; WATTAGE: 1/16W; fp_ECN: 0402 SERIES_LL34.xls
R230 R756 R761 R762 R766 R773 = R: RES CHIP 1K 1/16W +-1% (0402); CLASS: DISCRETE; CMPLS_LVL: EP; Data: WTC_LF_WR SERIES.pdf; Lifecycle: Comp-Approve; MATERIAL: CHIP; Manuf_PN: RR0510S-102-FN; Manuf_name: CYNTEC CO.. LTD.; Manuftr: CYN; Part_Type: *LF_Resistor; Status: Preferred; TOLERANCE: 1%; WATTAGE: 1/16W; fp_ECN: 0402 SERIES_LL34.xls
R322 = R: RES CHIP 8.2K 1/16W +-1%(0402); CLASS: DISCRETE; CMPLS_LVL: EP; Data: WTC_LF_WR SERIES-4.pdf; From_pj: S50-STRVE; Lifecycle: Comp-Approve; MATERIAL: CHIP; Manuf_PN: RM04FTN8201; Manuf_name: WALSIN TECHNOLOGY CORPORATION; Manuftr: WTC; Part_Type: *LF_Resistor; Standard: ##; TOLERANCE: 1%; WATTAGE: 1/16W; fp_ECN: 0402 SERIES_LL34.xls
R361 = R: RES CHIP 1K 1/20W +-1%(0201); CLASS: DISCRETE; CMPLS_LVL: EP(V1); Data: YGO_RC SERIES_A.pdf; From_pj: S2X-CAGE; Lifecycle: Comp-Approve; MATERIAL: CHIP; Manuf_PN: RC0201FR-071KL; Manuf_name: YAGEO CORPORATION; Manuftr: YGO; Not_insert: NI; Part_Type: *LF_Resistor; RD_CMPLS_LVL: EP(V1); TOLERANCE: 1%; WATTAGE: 1/20W; fp_ECN: DCN-all 0201 RCL part.doc
R590 R743 = R: RES CHIP 10K 1/16W +-1% (0402); CLASS: DISCRETE; CMPLS_LVL: EP; Data: WTC_LF_WR SERIES.pdf; From_pj: S82; Lifecycle: Comp-Approve; MATERIAL: CHIP; Manuf_PN: RR0510S-103-FN; Manuf_name: CYNTEC CO.. LTD.; Manuftr: CYN; Not_insert: NI; Part_Type: *LF_Resistor; Status: Preferred; TOLERANCE: 1%; WATTAGE: 1/16W; fp_ECN: 0402 SERIES_LL34.xls
C111 C476 C477 PC233 PC234 PC238 PC239 PC255-PC257 = CAP_NP: CAP CHIP 47U 4V(+-20%.X6S.0805); CLASS: DISCRETE; CMPLS_LVL: EP(V1); Data: MUR_GRM21BC80G476M.pdf; From_pj: S2N-JUMP; Lifecycle: Comp-Approve; MATERIAL: X6S; Manuf_PN: GRM21BC80G476M; Manuf_name: MURATA ERIE N.A. INC TAIWAN BRANCH Okayama Murata Mfg.Co..Ltd.Wakura Murata Mfg.; Manuftr: MUR; Part_Type: *LF_C0805; RD_CMPLS_LVL: EP(V1); TOLERANCE: 20%; VOLTAGE: 4V
C140 = CAP_NP: CAP CHIP 0.01U 50V(+-10%.X7R.0603)EP; CLASS: DISCRETE; CMPLS_LVL: EP; Data: AVX_SMCCP.pdf; From_pj: T11; Lifecycle: Comp-Approve; MATERIAL: X7R; Manuf_PN: C1608X7R103KGTS; Manuf_name: ACER PERIPHERALS INC.(Darfon Electronics Corp.); Manuftr: API; Not_insert: NI; Part_Type: *LF_C0603; Standard: End of Design; Status: Normal; TOLERANCE: 10%; VOLTAGE: 50V
C143 = CAP_NP: CAP CHIP 1U 10V(+-10%,X7R,0603)SAM; CLASS: DISCRETE; CMPLS_LVL: EP(V1); From_pj: T2H-CF; Lifecycle: Comp-Approve; MATERIAL: X7R; Manuf_PN: CL10B105KP8NNNC; Manuf_name: SAMSUNG ELECTRONICS CO.,LTD (Samsung Mobile Display)SAMSUNG SDI CO.,LTD; Manuftr: SAM; Part_Type: *LF_C0603; RD_CMPLS_LVL: EP(V1); TOLERANCE: 10%; VOLTAGE: 10V
C312 C313 C318 C320-C323 C327 C330 C336 C341 C343 C346-C350 C352 C358-C362 C379 C394 C399 C408 C443 C450 C451 = CAP_NP: CAP CHIP 22U 6.3V(+-20%,X6S,0603); CLASS: DISCRETE; Data: MUR_GRM155R72A221KA01-01.pdf; From_pj: F06-RAYMOND; Lifecycle: Comp-Approve; MATERIAL: X6S; Manuf_PN: GRM188C80J226M; Manuf_name: MURATA ERIE N.A. INC TAIWAN BRANCH Okayama Murata Mfg.Co.,; Manuftr: MUR; Part_Type: *LF_C0603; RD_CMPLS_LVL: EP(V1); TOLERANCE: 20%; VOLTAGE: 6.3V
C417 C424 = CAP_NP: CAP CHIP 0.1U 16V(10%.X7R.0402); CLASS: DISCRETE; CMPLS_LVL: EP(V1); Data: MUR_LF_CAP SERIES_1.pdf; From_pj: S5A-TRAVIS; Lifecycle: Comp-Approve; MATERIAL: X7R; Manuf_PN: WBM155R71C104K; Manuf_name: MURATA ERIE N.A. INC TAIWAN BRANCH Okayama Murata Mfg.Co..Ltd. Wakura Murata Mfg; Manufacturer: MUR; Manuftr: MUR; Part_Type: *LF_C0402; RD_CMPLS_LVL: EP(V1); TOLERANCE: 10%; VOLTAGE: 16V; fp_ECN: 0402 SERIES_LL34.xls
C420 = CAP_NP: CAP CHIP 4.7UF 6.3V(+-20%,X6S,0402); CLASS: DISCRETE; CMPLS_LVL: EP(V1); Data: MUR_JEMCG-4187DZ_20131126.pdf; From_pj: T6MG-ROGER; Lifecycle: Comp-Approve; MATERIAL: X6S; Manuf_PN: GRM155C80J475M; Manuf_name: MURATA ERIE N.A. INC TAIWAN BRANCH Okayama Murata Mfg.Co.,; Manuftr: MUR; Part_Type: *LF_C0402; RD_CMPLS_LVL: EP(V1); TOLERANCE: 20%; VOLTAGE: 6.3V; fp_ECN: 0402 SERIES_LL34.xls
C428 C432 C440 C452 = CAP_NP: CAP CHIP 1U.6.3V(+-10%.X7R.0402); CLASS: DISCRETE; CMPLS_LVL: EP(V1); Data: MKP_LF_CAP SERIES.pdf; From_pj: T94-JEFF; Lifecycle: Comp-Approve; MATERIAL: X7R; Manuf_PN: MAG02X7R0J105K; Manuf_name: Matsuki Precision Ceramic Co.. Ltd.Matsuki Polymer Technology Co.. Ltd.; Manuftr: MKP; Part_Type: *LF_C0402; RD_CMPLS_LVL: EP(V1); TOLERANCE: 10%; VOLTAGE: 6.3V; fp_ECN: 0402 SERIES_LL34.xls
C449 = CAP_NP: CAP CHIP 2.2UF 10V(+-10%,X6S,0402); CLASS: DISCRETE; CMPLS_LVL: EP(V1); From_pj: S5A-JOSHUA; Lifecycle: Comp-Approve; MATERIAL: X6S; Manuf_PN: GRM155C81A225K; Manuf_name: MURATA ERIE N.A. INC TAIWAN BRANCH Okayama Murata Mfg.Co.,Ltd.Wakura Murata Mfg.; Manuftr: MUR; Part_Type: *LF_C0402; RD_CMPLS_LVL: EP(V1); TOLERANCE: 10%; VOLTAGE: 10V
C472 C475 = CAP_NP: CAP CHIP 1U 10V(+-10%.X7R.0603); CLASS: DISCRETE; CMPLS_LVL: EP; Data: WTC_CAPACITOR SERIES.pdf; From_pj: T94-JEFF; Lifecycle: Comp-Approve; MATERIAL: X7R; Manuf_PN: 0603B105K100CT; Manuf_name: WALSIN TECHNOLOGY CORPORATION; Manuftr: WTC; Part_Type: *LF_C0603; Standard: End of Design; TOLERANCE: 10%; VOLTAGE: 10V
C484 C485 = CAP_NP: CAP CHIP 100U 4V(+-20%,X6S,0805)MUR; CLASS: DISCRETE; CMPLS_LVL: EP(V1); Data: MUR_GRM21BC80G107M.pdf; From_pj: T2H-CF; Lifecycle: Comp-Approve; MATERIAL: X6S; Manuf_PN: GRM21BC80G107M; Manuf_name: MURATA ERIE N.A. INC TAIWAN BRANCH Okayama Murata Mfg.Co.,Ltd.Wakura Murata Mfg.; Manuftr: MUR; Part_Type: *LF_C0805; RD_CMPLS_LVL: EP(V1); TOLERANCE: 20%; VOLTAGE: 4V
L12 L13 = L: IND CHIP 8.2NH +-5% 0.68A CS0402-8N2J-S; CLASS: DISCRETE; Current_Amp: 0.68A; Data: CLN_CS0402-8N2J-S.pdf; From_pj: F07-HENRY; Lifecycle: Comp-Approve; MATERIAL: IND; Manuf_PN: CS0402-8N2J-S; Manuf_name: CHILISIN ELECTRONICS CORP.; Manuftr: CLN; Part_Type: *LF_Inductor; RD_CMPLS_LVL: EP(V1)
R860 = R: RESISTOR CHIP 0 1/8W +-5%(0805); CLASS: DISCRETE; CMPLS_LVL: EP; Data: WTC_LF_WR SERIES.pdf; Lifecycle: Comp-Approve; MATERIAL: CHIP; Manuf_PN: ERJ6GEY0R00V; Manuf_name: MATSUSHITA ELECTRONICS CORPORATION (PANASONIC)Wuxi Matsushita Battery Co.. Ltd; Manuftr: MAT; Part_Type: *LF_Resistor; Standard: ##; Status: Normal; TOLERANCE: 5%; WATTAGE: 1/8W

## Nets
GND: C99.2 C102.2 C111.2 C120.2 C126.2 C140.2 C143.2 C151.2 C160.1 C164.1 C312.2 C313.2 C318.2 C320.2 C321.2 C322.2 C323.2 C327.2 C330.2 C336.2 C341.2 C343.2 C346.2 C347.2 C348.2 C349.2 C350.2 C352.2 C358.2 C359.2 C360.2 C361.2 C362.2 C379.2 C394.2 C399.2 C408.2 C417.1 C420.2 C424.1 C428.2 C432.2 C440.2 C443.2 C449.2 C450.2 C451.2 C452.2 C472.2 C475.2 C476.2 C477.2 C484.2 C485.2 C710.2 PC233.2 PC234.2 PC238.2 PC239.2 PC255.2 PC256.2 PC257.2 R177.1 R179.2 R261.1 R271.1 R300.2 R306.1 R322.1 R404.2 R428.1 R429.1 R501.1 R502.1 R582.1 R585.1 R586.1 R626.2 R627.1 R636.2 R646.2 R648.1 R651.1 R656.1 R657.1 R743.2 R756.1 R761.1 R762.1 R765.1 R766.1 R773.1 U53.4(GND) Y3.2(G1) Y3.4(G2) ; also on sheet 1 2 3 4 11 12 13 14 15 16 17 18 19 20 22 23 24 25 26 27 28 31 32 41 42 45 46 52 53 54 55 56 57 58 59 60 61 62 63 64 65 66 67 68 69 70 71 72 73 74 75 77 79 81 82 83 84 86 87 88 92
P1V05_COMBINED: C111.1 C432.1 C440.1 C443.1 C449.1 C450.1 C451.1 C452.1 C484.1 C485.1 L12.1 L13.1 PC233.1 PC234.1 PC238.1 PC239.1 PC255.1 PC256.1 PC257.1 R191.1 R343.1 R361.2 R605.1 R606.1 R608.1 R613.1 R621.1 R637.1 R638.1 R745.2 U30.AA58(VCCGBE0) U30.R48(VCCSCSUS5) U30.R49(VCCSCSUS4) U30.R58(VCCGBE10) U30.T48(VCCSCSUS3) U30.T49(VCCSCSUS2) U30.T51(VCCGBE9) U30.T53(VCCGBE8) U30.V48(VCCSCSUS1) U30.V49(VCCSCSUS0) U30.V51(VCCGBE7) U30.V53(VCCGBE6) U30.V56(VCCGBE5) U30.V58(VCCGBE4) U30.Y53(VCCGBE3) U30.Y56(VCCGBE2) U30.Y58(VCCGBE1) ; also on sheet 1 3 4 16 18 19 41 42 45 52 54 55 56 63 71 74 75 79 84 92 94
P1V5_PCH: R655.1 R660.2 U30.V33(SOC_IREF) U30.W20(ICLK_IREF) ; also on sheet 31 46 52 94
P1V05_PCH: R590.2 R860.2 ; also on sheet 52 63 67 74 84
P1V05_PCH_FILT: C140.1 C143.1 R860.1 U30.AE27(VCCAXCK1_05)
P3V3: C164.2 R188.2 R200.1 R224.2 R230.1 R234.2 R265.2 R391.1 U53.1(VDD) ; also on sheet 4 19 20 32 41 42 46 52 55 56 63 67 74 77 81
PVCCGBE_VCCKRL: C472.1 C476.1 L13.2 U30.T56(VCCKRLCPLL)
PVCCGBE_VCCS: C475.1 C477.1 L12.2 U30.T46(VCCSCPLL)
PVCCIN: C313.1 C320.1 C327.1 C330.1 C336.1 C341.1 C343.1 C346.1 C347.1 C348.1 C349.1 C350.1 C352.1 C358.1 C359.1 C360.1 C361.1 C362.1 C379.1 C394.1 C399.1 C408.1 C420.1 U30.AG53(VCCIN57) U30.AG55(VCCIN58) U30.AV60(VCCIN0) U30.AW55(VCCIN1) U30.AW56(VCCIN2) U30.AW58(VCCIN3) U30.AW62(VCCIN4) U30.AW66(VCCIN5) U30.AW69(VCCIN6) U30.AW72(VCCIN7) U30.AW74(VCCIN8) U30.AW76(VCCIN9) U30.AW78(VCCIN10) U30.AY60(VCCIN11) U30.AY64(VCCIN12) U30.AY67(VCCIN13) U30.AY71(VCCIN14) U30.AY75(VCCIN15) U30.AY77(VCCIN16) U30.BA58(VCCIN17) U30.BA62(VCCIN18) U30.BA66(VCCIN19) U30.BA69(VCCIN20) U30.BA72(VCCIN21) U30.BA74(VCCIN22) U30.BA76(VCCIN23) U30.BA78(VCCIN24) U30.BB36(VCCIN25) U30.BB56(VCCIN26) U30.BB60(VCCIN27) U30.BB64(VCCIN28) U30.BB67(VCCIN29) U30.BB71(VCCIN30) U30.BB75(VCCIN31) U30.BB77(VCCIN32) U30.BC58(VCCIN33) U30.BC62(VCCIN34) U30.BC66(VCCIN35) U30.BC69(VCCIN36) U30.BC72(VCCIN37) U30.BD36(VCCIN38) U30.BD37(VCCIN39) U30.BD56(VCCIN40) U30.BD60(VCCIN41) U30.BD64(VCCIN42) U30.BD67(VCCIN43) U30.BD71(VCCIN44) U30.BD74(VCCIN45) U30.BD76(VCCIN46) U30.BD78(VCCIN47) U30.BE37(VCCIN48) U30.BE58(VCCIN49) U30.BE62(VCCIN50) U30.BF60(VCCIN51) U30.BG37(VCCIN52) U30.BG58(VCCIN53) U30.BH37(VCCIN54) U30.BH56(VCCIN55) U30.BJ56(VCCIN56) ; also on sheet 2 3
PVCCKRHV: C424.2 U30.N51(VCCKX4PLL) U30.N58(VCCKRHV) ; also on sheet 26
PVCCSCFUSESUS: C417.2 C428.1 U30.AA53(VCCSCFUSESUS1) U30.AA55(VCCSCFUSESUS0) U30.AE53(VCCSCFUSESUS3) U30.AE55(VCCSCFUSESUS2) ; also on sheet 26 27 31
BATLOW_N_BUF: U30.AU14(TACH6_GPIO70) ; also on sheet 20
BMC_PWR_BTN_OUT_N: U30.AW3(PWRBTN_N) ; also on sheet 72
BMC_READY_N: U30.BA5(GPIO25) ; also on sheet 72
BMC_TI_PECI: R217.2 ; also on sheet 71
CLK_33M_COME_LPC: R387.2 ; also on sheet 65
CLK_33M_COME_LPC_R: R387.1 U53.7(Q3)
CLK_33M_ICS553: R640.2 U53.5(ICLK)
CLK_33M_ICS553_R: R640.1 U30.AA9(CLKOUT_PCI0)
CLK_33M_LPC_ICS553: R389.1 U53.3(Q1)
CLK_33M_PCICLKIN: R379.2 U30.AC7(CLKIN_PCILOOPBACK)
CLK_33M_PCICLKIN_R: R379.1 U53.6(Q2)
CLK_33M_SERIRQ: R399.2 R404.1 U30.AC67(SERIRQ_CLK)
CLK_33M_SERIRQ_R: R399.1 U53.2(Q0)
CLK_33M_TI_LPC: R389.2 ; also on sheet 72
CLK_100M_I210_DN: U30.R2(CLKOUT_PCIE_DN5) ; also on sheet 87
CLK_100M_I210_DP: U30.R4(CLKOUT_PCIE_DP5) ; also on sheet 87
CLK_100M_PE_A_DN: U30.U2(CLKOUT_PCIE_DN0) ; also on sheet 13
CLK_100M_PE_A_DP: U30.U4(CLKOUT_PCIE_DP0) ; also on sheet 13
CLK_100M_XDP_R_DN: U30.H2(CLKOUT_ITPXDP_DN) ; also on sheet 54
CLK_100M_XDP_R_DP: U30.H4(CLKOUT_ITPXDP_DP) ; also on sheet 54
CLK_CPLD_SUSCLK: R134.1 ; also on sheet 14 41
CLK_CPLD_SUSCLK_R: R134.2 U30.BD11(SUSCLK_GPIO62)
DMI_RCOMP_PCH: R655.2 U30.AA28(SOC_RCOMP)
DRAM_PWROK: U30.BA9(DRAMPWROK_PCH) ; also on sheet 18
ERROR_BDE_0: U30.AC77(ERROR_N0) ; also on sheet 56
ERROR_BDE_1: U30.AC75(ERROR_N1) ; also on sheet 56
ERROR_BDE_2: U30.AB76(ERROR_N2) ; also on sheet 56
FAST_THROTTLE_N_R: U30.BB21(GPIO24_MGPIO0) ; also on sheet 64 65 71
FM_ADR_TRIGGER_PCH_N: U30.AD66(ADR_IN) ; also on sheet 63
FM_BDXDE_CATERR_LVT3_N: U30.BW22(PIRQH_N_GPIO5) ; also on sheet 56 64 72
FM_BDXDE_ERR0_LVT3_N: U30.BV16(PIRQE_N_GPIO2) ; also on sheet 56 64 72
FM_BDXDE_ERR1_LVT3_N: U30.BN22(PIRQF_N_GPIO3) ; also on sheet 56 64 72
FM_BDXDE_ME_DRIVE_N: U30.BB23(GPIO28_MGPIO7) ; also on sheet 63 64
FM_BDXDE_RESET_N: C151.1 U30.BU7(PLTRST_PROC_N) U30.L76(RESET_CPU_N) ; also on sheet 54 56
FM_BDXDE_SLP3_CPU_N: U30.AC71(SLP_S3_CPU_N) ; also on sheet 14
FM_BDXDE_SLP3_N_R: U30.AY2(SLP_S3_N) ; also on sheet 63
FM_BDXDE_SLP4_N_R: U30.AW1(SLP_S4_N) ; also on sheet 63
FM_BDXDE_SLP_A_N: U30.BB7(SLP_A_N) ; also on sheet 63
FM_BDXDE_SMI_N: R137.1 ; also on sheet 63 67
FM_BDXDE_THERMTRIP_N: U30.AF72(THERMTRIP_N) ; also on sheet 56 63
FM_BDXDE_THERMTRIP_PCH_N: U30.BJ16(THERMTRIP_PCH_N) ; also on sheet 67
FM_BIOS_POST_CMPLT_N: U30.BA19(GPIO46) ; also on sheet 67
FM_CPLD_GPIO27_MGPIO6: U30.BB16(GPIO27_MGPIO6) ; also on sheet 63 64
FM_CPU2PCH_THROT: U30.AL74(THROTTLE_PECI_ID2) ; also on sheet 42 55
FM_CPU2PCH_THROT_LVT3: U30.BL22(PIRQG_N_GPIO4) ; also on sheet 55
FM_NMI_EVENT_N_NOA_CLK2: R142.2 ; also on sheet 63 67
FM_SRC1CLKRQB_GP18: U30.BN4(SRC1CLKRQ_N_GPIO18) ; also on sheet 63
H_BDE_CATERR_GTL_N: R847.1 ; also on sheet 56
H_BDE_CATERR_GTL_R_N: R343.2 R847.2 U30.Y67(CATERR_N)
H_BDXDE_FIVR_FAULT: U30.AP69(FIVR_FAULT) ; also on sheet 56
H_BDXDE_PROCHOT_DISABLE: U30.BB12(SLP_WLAN_N_GPIO29_MGPIO3) ; also on sheet 63 64
H_PROCHOT_CO_N: U30.AG71(PROCHOT_N) U30.CC56(MEM_HOT_N) ; also on sheet 55
ICS553_OE: C160.2 R391.2 U53.8(OE)
IRQ_BMC_PCH_NMI_NOA1_CLK: U30.BJ4(GPIO8_OCS) ; also on sheet 71 72
IRQ_IBMC_PCH_SMI_LPC_N: U30.BD26(LAN_PHY_PWR_CTRL_GPIO12) ; also on sheet 63 71
IRQ_ILB_SEIRQ_BDE: U30.BU14(SERIRQ) ; also on sheet 19 63
IRQ_PIRQA_N: R234.1 U30.BG20(PIRQA_N) ; also on sheet 62
LPC_FRAME_N: R229.1 ; also on sheet 65 72
LPC_FRAME_R_N: R229.2 U30.AH1(LFRAME_N)
LPC_LAD0: R251.1 ; also on sheet 65 72
LPC_LAD0_R: R251.2 U30.AF3(LAD0)
LPC_LAD1: R239.1 ; also on sheet 65 72
LPC_LAD1_R: R239.2 U30.AG4(LAD1)
LPC_LAD2: R221.1 ; also on sheet 65 72
LPC_LAD2_R: R221.2 U30.AL3(LAD2)
LPC_LAD3: R243.1 ; also on sheet 65 72
LPC_LAD3_R: R243.2 U30.AF1(LAD3)
MFG_MODE_STRAP: U30.BD22(MFG_MODE_STRAP) ; also on sheet 4
NMI_BDE_R: R142.1 U30.BP1(GPIO35_NMI_N)
PCHHOT_CPU_N: U30.AL76(PCHHOT_CPU_N) ; also on sheet 18 56
PD_BIST_ENABLE: U30.AM69(BIST_ENABLE) ; also on sheet 42
PD_CLKIN_CPY_DN: R651.2 U30.Y30(CLKIN_GND1_DN)
PD_CLKIN_CPY_DP: R648.2 U30.AA30(CLKIN_GND1_DP)
PD_CLKIN_DMI_DN: R428.2 U30.N35(CLKIN_GND2_DN)
PD_CLKIN_DMI_DP: R429.2 U30.P33(CLKIN_GND2_DP)
PD_CLKIN_DOT96_DN: R261.2 U30.AB1(CLKIN_GND3_DN)
PD_CLKIN_DOT96_DP: R271.2 U30.AB3(CLKIN_GND3_DP)
PD_CLKIN_SATA_DN: R585.2 U30.BG32(CLKIN_GND4_DN)
PD_CLKIN_SATA_DP: R586.2 U30.BH33(CLKIN_GND4_DP)
PD_DMI_RX_TERMINATION: U30.AN11(GPIO33) ; also on sheet 42
PD_GPIO52_CPUSV: U30.BP16(GPIO52) ; also on sheet 41
PD_GPIO53_GSXDIN: U30.BT20(GPIO53) ; also on sheet 42
PD_NCTF_TP11_P11: R322.2 U30.P11(NCTF_TP11)
PD_P1V2_VDDQ_SEL_N: U30.BA23(GPIO15) ; also on sheet 63
PD_REFCLK14IN: R656.2 U30.W9(REFCLK14IN)
PD_RSVD1_AK66: R627.2 U30.AK66(RSVD1)
PD_RSVD2_E72: R765.2 U30.E72(RSVD2)
PD_RSVD16_F54: R761.2 U30.F54(RSVD16)
PD_RSVD17_J54: R762.2 U30.J54(RSVD17)
PD_RSVD21_AP75: R177.2 U30.AP75(RSVD21)
PD_RSVD84_AA66: R657.2 U30.AA66(RSVD84)
PD_RSVD93_A73: R766.2 U30.A73(RSVD93)
PD_RSVD94_A74: R756.2 U30.A74(RSVD94)
PD_RSVD95_A76: R743.1 U30.A76(RSVD95)
PD_SPARE<1>: R638.2 R646.1 U30.AC64(RSVD9)
PD_SPARE<2>: R179.1 R191.2 U30.AN78(RSVD10)
PD_SPARE<3>: R636.1 R637.2 U30.AG67(RSVD11)
PD_SPARE<4>: R613.2 R626.1 U30.AJ67(RSVD12)
PD_SPEAKER_PCH: U30.BP20(SPKR) ; also on sheet 42
PD_TEST<0>: R501.2 U30.CU76(TEST0)
PD_TEST<1>: R502.2 U30.CM78(TEST1)
PD_TEST_RSVD18_E55: R361.1 R773.2 U30.E55(RSVD18)
PD_TXT_AGENT: U30.AM72(TXT_AGENT) ; also on sheet 41
PD_TXT_PLTEN: U30.AP72(TXT_PLTEN) ; also on sheet 41
PECI_CPU: R217.1 R582.2 R859.2 U30.AL78(PECI_CPU)
PECI_ID[0]: U30.L72(PECI_ID0) ; also on sheet 63
PECI_PCH: R219.1 U30.BG16(PECI_PCH)
PECI_PCH_CPU: R219.2 R859.1
PLTRST_R_N: R276.2 U30.BE24(PLTRST_N)
PMSYNC_CPU_PCH: U30.BT9(PM_SYNC_PCH) U30.H77(PMSYNC_CPU)
PU_BIOS_RCVR_BOOT_J2: U30.BU22(GPIO55) ; also on sheet 4
PU_BMBUSY_N_GPIO0: U30.BB28(BMBUSY_N_GPIO0) ; also on sheet 63
PU_BMCINIT: U30.AD69(BMCINIT) ; also on sheet 63
PU_DIFFCLK_BIASREF: R660.1 U30.AA18(DIFFCLK_BIASREF)
PU_DSWODVREN: U30.AL1(DSWODVREN) ; also on sheet 63
PU_EAR_N: R608.2 U30.AH62(EAR_N)
PU_GP50_GSXCLK: U30.BV20(GPIO50) ; also on sheet 63
PU_GP54_GSXSREST_N: U30.BW18(GPIO54) ; also on sheet 63
PU_GPIO51_GSXDOUT: U30.BL18(GPIO51) ; also on sheet 42
PU_GPIO57_ME_RCVR_N: U30.BP9(GPIO57_MGPIO5) ; also on sheet 4
PU_GPIO72_BATLOW_N: U30.BB4(GPIO72) ; also on sheet 63
PU_INTVRMEN: U30.AP2(INTVRMEN) ; also on sheet 63
PU_MBP0_MBPM1_N: U30.AD72(BPM_N1) U30.W75(BPM_N0) ; also on sheet 16
PU_NCTF_TP3_BA27: R230.2 U30.BA27(NCTF_TP3)
PU_NCTF_TP4_BA18: R590.1 U30.BA18(NCTF_TP4)
PU_PIRQB_N: R265.1 U30.BF22(PIRQB_N)
PU_PIRQC_N: R224.1 U30.AR11(PIRQC_N)
PU_PIRQD_N: R188.1 U30.BH22(PIRQD_N)
PU_PME_N: U30.BE16(PME_N) ; also on sheet 63
PU_RI_N: U30.BF11(RI_N) ; also on sheet 63
PU_RSVD0_BL14: R200.2 U30.BL14(RSVD0)
PU_RSVD13_D71: R745.1 U30.D71(RSVD13)
PU_SAFE_MODE_BOOT: U30.AF69(SAFE_MODE_BOOT) ; also on sheet 42
PU_SPI_BDE_CS1_N: U30.BT13(SPI_CS1_N) ; also on sheet 63
PU_SUSACK_N: U30.AY4(SUSACK_N) ; also on sheet 63
PU_SUSWARN_N_GPIO30: U30.AY11(SUSWARN_N_SUSPWRDNACK_GPIO30) ; also on sheet 63
PV_VDDRAB: C312.1 C318.1 C321.1 C322.1 C323.1 U30.CF60(VCCD33) U30.CG43(VCCD0) U30.CG51(VCCD1) U30.CG54(VCCD2) U30.CG58(VCCD3) U30.CH33(VCCD4) U30.CH37(VCCD5) U30.CH41(VCCD6) U30.CH45(VCCD7) U30.CH49(VCCD8) U30.CH56(VCCD9) U30.CJ39(VCCD12) U30.CK52(VCCD10) U30.CK60(VCCD11) U30.CL35(VCCD13) U30.CL58(VCCD34) U30.CP38(VCCD14) U30.CP40(VCCD15) U30.CP42(VCCD16) U30.CP44(VCCD17) U30.CP47(VCCD18) U30.CP49(VCCD19) U30.CP51(VCCD20) U30.CP53(VCCD21) U30.CP55(VCCD22) U30.CP58(VCCD23) U30.CP60(VCCD24) U30.CP62(VCCD38) U30.CP68(VCCD37) U30.CT55(VCCD25) U30.CU39(VCCD26) U30.CU43(VCCD27) U30.CU48(VCCD28) U30.CU52(VCCD29) U30.CU59(VCCD30) U30.CU63(VCCD31) U30.CU65(VCCD36) U30.CU67(VCCD32) U30.CU69(VCCD35) ; also on sheet 11 15 22 23 24 60 61 74
PWRGD_APWROK: R300.1 U30.BE13(APWROK) ; also on sheet 14
PWRGD_BDXDE_LAN: U30.AE77(LAN_PWRGOOD) ; also on sheet 54 55
PWRGD_CPU: U30.BU11(PROCPWRGD_PCH) U30.V76(PWRGOOD_CPU) ; also on sheet 18 54 56 63
PWRGD_PCH_PWROK: C710.1 U30.AN1(PCH_PWROK) ; also on sheet 13 14 71
REV_BDE_ID0: U30.AG2(TACH3_GPIO7) ; also on sheet 63
REV_BDE_ID1: U30.AV7(TACH4_GPIO68) ; also on sheet 63
RSM_RST_N: U30.AR7(RSMRST_N) U30.AV4(DPWROK) ; also on sheet 14 72
RST_CPU_RSMRST_N: R307.1 U30.R77(RSMRST_CPU_N) ; also on sheet 16
RST_CPU_RSMRST_N_R: R307.2 ; also on sheet 14
RST_PCH_SYS_RESET_N: U30.BL4(SYS_RESET_N) ; also on sheet 81
RST_PLTRST_N: R276.1 ; also on sheet 62 64 67
RST_RTCRST_N: U30.AP9(RTCRST_N) ; also on sheet 13
RST_SRTCRST_N: U30.AP4(SRTCRST_N) ; also on sheet 41
RTCX1: R183.2 U30.AT2(RTCX1)
RTCX1_R: C102.1 R183.1 R190.1 Y1.1
RTCX2: C99.1 R190.2 U30.AT4(RTCX2) Y1.2
SERIRQ_DATA: U30.AE75(SERIRQ_DATA) ; also on sheet 19
SERIRQ_DIR: U30.AD74(SERIRQ_DIR) ; also on sheet 4 19
SKU_BDE_ID0: U30.AN3(TACH0_GPIO17) ; also on sheet 63
SKU_BDE_ID1: U30.AM4(TACH1_GPIO1) ; also on sheet 63
SKU_BDE_ID2: U30.AV11(TACH2_GPIO6) ; also on sheet 63
SLP_SUS_STAT_N_R: U30.BB18(SUS_STAT_N_GPIO61) ; also on sheet 63
SMB_INA230_ALRT_N: U30.BC9(GPIO31_MGPIO2) ; also on sheet 86
SMI_BMC_N_R: R137.2 U30.BR4(GPIO20_SMI_N)
SPI_BDE_CLK: R1321.1 U30.BG13(SPI_CLK) ; also on sheet 59
SPI_BDE_CS0_N: U30.BN7(SPI_CS0_N) ; also on sheet 59
SPI_BDE_CS2_N: U30.BJ9(SPI_CS2_N) ; also on sheet 62 63
SPI_BDE_HOLD_IO3: U30.BE20(SPI_IO3) ; also on sheet 57
SPI_BDE_MISO: U30.BJ20(SPI_MISO_IO1) ; also on sheet 59 62
SPI_BDE_MOSI: R1318.1 U30.BL11(SPI_MOSI_IO0) ; also on sheet 59
SPI_BDE_WP_IO2: U30.BF18(SPI_IO2) ; also on sheet 57
SPI_TPM_CLK_CHIP: R1321.2 ; also on sheet 62
SPI_TPM_MOSI_CHIP: R1318.2 ; also on sheet 62
SVID_CPU_ALERT_N: R604.2 R605.2 ; also on sheet 3 24
SVID_CPU_ALERT_N_R: R604.1 U30.AK72(SVIDALERT_N)
SVID_CPU_CLK: R620.2 R621.2 ; also on sheet 3 24
SVID_CPU_CLK_R: R620.1 U30.AH72(SVIDCLK)
SVID_CPU_DATA: R606.2 R616.2 ; also on sheet 3 24
SVID_CPU_DATA_R: R616.1 U30.AJ71(SVIDDATA)
TP_CLK_33M_LPC: U30.Y7(CLKOUT_PCI1)
TP_CLK_33M_PCH: U30.AA4(CLKOUT_PCI2)
TP_CPU_SLP_SUS_N: U30.AY7(SLP_SUS_N)
TP_FM_ADR_COMPLETE: U30.AF66(ADR_COMPLETE)
TP_GPIO26: U30.BB14(GPIO26)
TP_GPIO32: U30.BB27(GPIO32)
TP_GPIO44: U30.BD18(GPIO44)
TP_GPIO45: U30.BA21(GPIO45)
TP_NCTF_TP0_BF33: U30.BF33(NCTF_TP0)
TP_NCTF_TP1_BE32: U30.BE32(NCTF_TP1)
TP_NCTF_TP2_BD7: U30.BD7(NCTF_TP2)
TP_NCTF_TP5_BA14: U30.BA14(NCTF_TP5)
TP_NCTF_TP6_AN7: U30.AN7(NCTF_TP6)
TP_NCTF_TP7_AD9: U30.AD9(NCTF_TP7)
TP_NCTF_TP8_AC11: U30.AC11(NCTF_TP8)
TP_NCTF_TP9_T37: U30.T37(NCTF_TP9)
TP_NCTF_TP10_T35: U30.T35(NCTF_TP10)
TP_NCTF_TP12_K11: U30.K11(NCTF_TP12)
TP_NCTF_TP13_J20: U30.J20(NCTF_TP13)
TP_NCTF_TP14_H11: U30.H11(NCTF_TP14)
TP_NCTF_TP15_F20: U30.F20(NCTF_TP15)
TP_PCH_DRQ0_N: U30.AK4(LDRQ0_N)
TP_PCH_DRQ1_N: U30.AL5(LDRQ1_N_GPIO23)
TP_PWM0: U30.AW12(PWM0)
TP_RSVD3_H71: U30.H71(RSVD3)
TP_RSVD4_K71: U30.K71(RSVD4)
TP_RSVD5_J69: U30.J69(RSVD5)
TP_RSVD6_F69: U30.F69(RSVD6)
TP_RSVD7_K64: U30.K64(RSVD7)
TP_RSVD8_H64: U30.H64(RSVD8)
TP_RSVD14_N54: U30.N54(RSVD14)
TP_RSVD15_L54: U30.L54(RSVD15)
TP_RSVD19_W66: U30.W66(RSVD19)
TP_RSVD20_Y64: U30.Y64(RSVD20)
TP_RSVD22_AM56: U30.AM56(RSVD22)
TP_RSVD23_AP55: U30.AP55(RSVD23)
TP_RSVD24_AM55: U30.AM55(RSVD24)
TP_RSVD25_BL60: U30.BL60(RSVD25)
TP_RSVD26_BJ62: U30.BJ62(RSVD26)
TP_RSVD27_V40: U30.V40(RSVD27)
TP_RSVD28_CA37: U30.CA37(RSVD28)
TP_RSVD29_AP60: U30.AP60(RSVD29)
TP_RSVD30_AP56: U30.AP56(RSVD30)
TP_RSVD31_AK56: U30.AK56(RSVD31)
TP_RSVD32_BL37: U30.BL37(RSVD32)
TP_RSVD33_AG56: U30.AG56(RSVD33)
TP_RSVD34_BP37: U30.BP37(RSVD34)
TP_RSVD35_AE56: U30.AE56(RSVD35)
TP_RSVD36_BT37: U30.BT37(RSVD36)
TP_RSVD37_AC56: U30.AC56(RSVD37)
TP_RSVD38_BW37: U30.BW37(RSVD38)
TP_RSVD39_T42: U30.T42(RSVD39)
TP_RSVD40_T40: U30.T40(RSVD40)
TP_RSVD41_T44: U30.T44(RSVD41)
TP_RSVD42_BP58: U30.BP58(RSVD42)
TP_RSVD43_R44: U30.R44(RSVD43)
TP_RSVD44_BP56: U30.BP56(RSVD44)
TP_RSVD45_CB43: U30.CB43(RSVD45)
TP_RSVD46_CB39: U30.CB39(RSVD46)
TP_RSVD47_BM62: U30.BM62(RSVD47)
TP_RSVD48_V39: U30.V39(RSVD48)
TP_RSVD49_Y33: U30.Y33(RSVD49)
TP_RSVD50_BU60: U30.BU60(RSVD50)
TP_RSVD51_Y37: U30.Y37(RSVD51)
TP_RSVD52_BR60: U30.BR60(RSVD52)
TP_RSVD53_V37: U30.V37(RSVD53)
TP_RSVD54_Y35: U30.Y35(RSVD54)
TP_RSVD55_Y32: U30.Y32(RSVD55)
TP_RSVD56_A66: U30.A66(RSVD56)
TP_RSVD57_C66: U30.C66(RSVD57)
TP_RSVD58_B54: U30.B54(RSVD58)
TP_RSVD59_D54: U30.D54(RSVD59)
TP_RSVD60_A55: U30.A55(RSVD60)
TP_RSVD61_C55: U30.C55(RSVD61)
TP_RSVD62_AE58: U30.AE58(RSVD62)
TP_RSVD63_AG58: U30.AG58(RSVD63)
TP_RSVD64_AE62: U30.AE62(RSVD64)
TP_RSVD65_AM66: U30.AM66(RSVD65)
TP_RSVD66_AE60: U30.AE60(RSVD66)
TP_RSVD67_AN64: U30.AN64(RSVD67)
TP_RSVD68_AK58: U30.AK58(RSVD68)
TP_RSVD69_AP58: U30.AP58(RSVD69)
TP_RSVD70_AC60: U30.AC60(RSVD70)
TP_RSVD71_AC62: U30.AC62(RSVD71)
TP_RSVD72_AG60: U30.AG60(RSVD72)
TP_RSVD73_AH58: U30.AH58(RSVD73)
TP_RSVD74_AG64: U30.AG64(RSVD74)
TP_RSVD75_AH60: U30.AH60(RSVD75)
TP_RSVD76_AM58: U30.AM58(RSVD76)
TP_RSVD77_AM60: U30.AM60(RSVD77)
TP_RSVD78_AP66: U30.AP66(RSVD78)
TP_RSVD79_AR64: U30.AR64(RSVD79)
TP_RSVD80_AP62: U30.AP62(RSVD80)
TP_RSVD81_AM62: U30.AM62(RSVD81)
TP_RSVD82_AK62: U30.AK62(RSVD82)
TP_RSVD83_AJ64: U30.AJ64(RSVD83)
TP_RSVD85_N43: U30.N43(RSVD85)
TP_RSVD86_N47: U30.N47(RSVD86)
TP_RSVD87_R39: U30.R39(RSVD87)
TP_RSVD88_N39: U30.N39(RSVD88)
TP_RSVD89_C49: U30.C49(RSVD89)
TP_RSVD90_A49: U30.A49(RSVD90)
TP_RSVD91_Y60: U30.Y60(RSVD91)
TP_RSVD92_Y62: U30.Y62(RSVD92)
TP_RSVD96_BT62: U30.BT62(RSVD96)
TP_RSVD97_AR71: U30.AR71(RSVD97)
TPM_PRSNT_N: U30.AU9(TACH5_GPIO69) ; also on sheet 62 63
UART1_BDE_R2_TXD: R237.1 U30.AG75(UART_TXD0) ; also on sheet 19
UART1_BDE_R_RXD: U30.AG77(UART_RXD0) ; also on sheet 19
UART1_BDE_R_TXD: R237.2 ; also on sheet 19
UART_BDE_BMC_R_TX: R226.1 U30.AH76(UART_TXD1) ; also on sheet 19
UART_BDE_BMC_RX: U30.AH78(UART_RXD1) ; also on sheet 19
UART_BDE_BMC_TX: R226.2 ; also on sheet 19
WAKE_N_R: U30.BA1(WAKE_N) ; also on sheet 56
WAKELAN_N: R275.1 ; also on sheet 56
WAKELAN_N_R: R275.2 U30.AD76(WAKELAN_N)
XDP_BDE_PRDY_N: U30.L78(PRDY_N) ; also on sheet 16 54
XDP_BDE_PREQ_N: U30.K77(PREQ_N) ; also on sheet 16 54
XDP_BDE_TCK: R306.2 U30.T76(JTAG_TCK_CPU) ; also on sheet 54
XDP_BDE_TDI: U30.V78(JTAG_TDI_CPU) ; also on sheet 16 54
XDP_BDE_TDO: R858.1 ; also on sheet 16 54
XDP_BDE_TDO_R: R858.2 U30.T78(JTAG_TDO_CPU)
XDP_BDE_TMS: U30.R75(JTAG_TMS_CPU) ; also on sheet 16 54
XDP_BDE_TRST_N: U30.U75(JTAG_TRST_N_CPU) ; also on sheet 16 54
XDP_CPU_OBSDATA_A_MBP2_N: U30.N78(BPM_N2) ; also on sheet 16 54
XDP_CPU_OBSDATA_A_MBP3_N: U30.M75(BPM_N3) ; also on sheet 16 54
XDP_CPU_OBSDATA_A_MBP4_N: U30.J78(BPM_N4) ; also on sheet 16 54
XDP_CPU_OBSDATA_A_MBP5_N: U30.H75(BPM_N5) ; also on sheet 16 54
XDP_CPU_OBSFN_B_MBP6_N: U30.K75(BPM_N6) ; also on sheet 16 54
XDP_CPU_OBSFN_B_MBP7_N: U30.J76(BPM_N7) ; also on sheet 16 54
XDP_CPU_PWR_DEBUG_N: U30.U77(PWR_DEBUG_N) ; also on sheet 16 54
XDP_CPU_SYSPWROK: U30.BP5(SYS_PWROK) ; also on sheet 14 16 54 71
XDP_PCH_TCK0: U30.BM3(JTAG_TCK_PCH) ; also on sheet 16
XDP_PCH_TDI: U30.BM5(JTAG_TDI_PCH) ; also on sheet 16
XDP_PCH_TDO: U30.BK3(JTAG_TDO_PCH) ; also on sheet 16
XDP_PCH_TMS: U30.BJ2(JTAG_TMS_PCH) ; also on sheet 16
XDP_PRESENT_N: U30.M77(DEBUG_EN_N) ; also on sheet 16 54
XTAL_CLKGEN_REFCLK_IN: R336.2 U30.K2(XTAL25_IN)
XTAL_CLKGEN_REFCLK_IN_R: C120.1 R336.1 R351.1 Y3.1(X1)
XTAL_CLKGEN_REFCLK_OUT: C126.1 R351.2 U30.J1(XTAL25_OUT) Y3.3(X2)

Not connected (* = marked no-connect by the designer): U30 AA2(CLKOUTFLEX3_GPIO67)* AC4(CLKOUTFLEX1_GPIO65)* AM2(TACH7_GPIO71)* M2(CLKOUT_PCIE_DP6)* M4(CLKOUT_PCIE_DN6)* N1(CLKOUT_PCIE_DN7)* N3(CLKOUT_PCIE_DP7)* N9(CLKOUT_PCIE_DP4)* P7(CLKOUT_PCIE_DP3)* R9(CLKOUT_PCIE_DN4)* T1(CLKOUT_PCIE_DN2)* T3(CLKOUT_PCIE_DP2)* T7(CLKOUT_PCIE_DN3)* V11(CLKOUT_PCI3)* W2(CLKOUT_PEG_DN)* W4(CLKOUT_PEG_DP)* Y1(CLKOUT_PCIE_DN1)* Y3(CLKOUT_PCIE_DP1)* Y11(CLKOUT_PCI4)*

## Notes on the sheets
sheet 47
- BDX-DE LPC,SPI,GPIO,INT,PWR_1
sheet 48
- BDX-DE UART,MGNT,INT,SVID_1
sheet 49
- BDX-DE CLK
sheet 50
- SPARE[1]
- 0
- 1'B0 = PMC FSB BRINGS UP SOUTH COMPLEX (DEFAULT)
  1'B1 = PCODE BRINGS UP SOUTH COMPLEX OF PMC
- SPARE[2]
- 0
- BYPASSES THE CRYSTAL CLOCK TO THE SCPLL
  1'B0 = PICKS THE 25MHZ KR CRYSTAL CLOCK AS THE REFERENCE TO SCPLL (DEDAULT)
  1'B1 = FORCES THE TEST DOCK FROM TSTCLK_SC PINS
- SPARE[3]
- 0
- SELECTS B/W FUNCTIONAL AND TEST MODE IN THE KX4 PLL
  1'B0 = NO TEST CLOCK OVERRIDE(DEFAULT)
  1'B1 = TEST CLOCK OVERRIDE
- SPARE[4]
- 0
- 1'B0 = NORMAL REFERENCE CLOCK PATH WITH CR BASE REFERENCE CLOCK SELECTION(DEFAULT)
  1'B1 = FORCE "REGULAR" REFERENCE CLOCKS TO BE SENT TO THE KX4 PLLS AS LONG AS TSTCLK_KX4_STRAP[2]=1'B0
- TEST
sheet 51
- These two items need double confirm with Intel.
- BDX-DE POWER_1
